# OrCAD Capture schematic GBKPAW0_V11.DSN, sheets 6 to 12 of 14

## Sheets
6 PAGE12:DCINV&P5V: size B
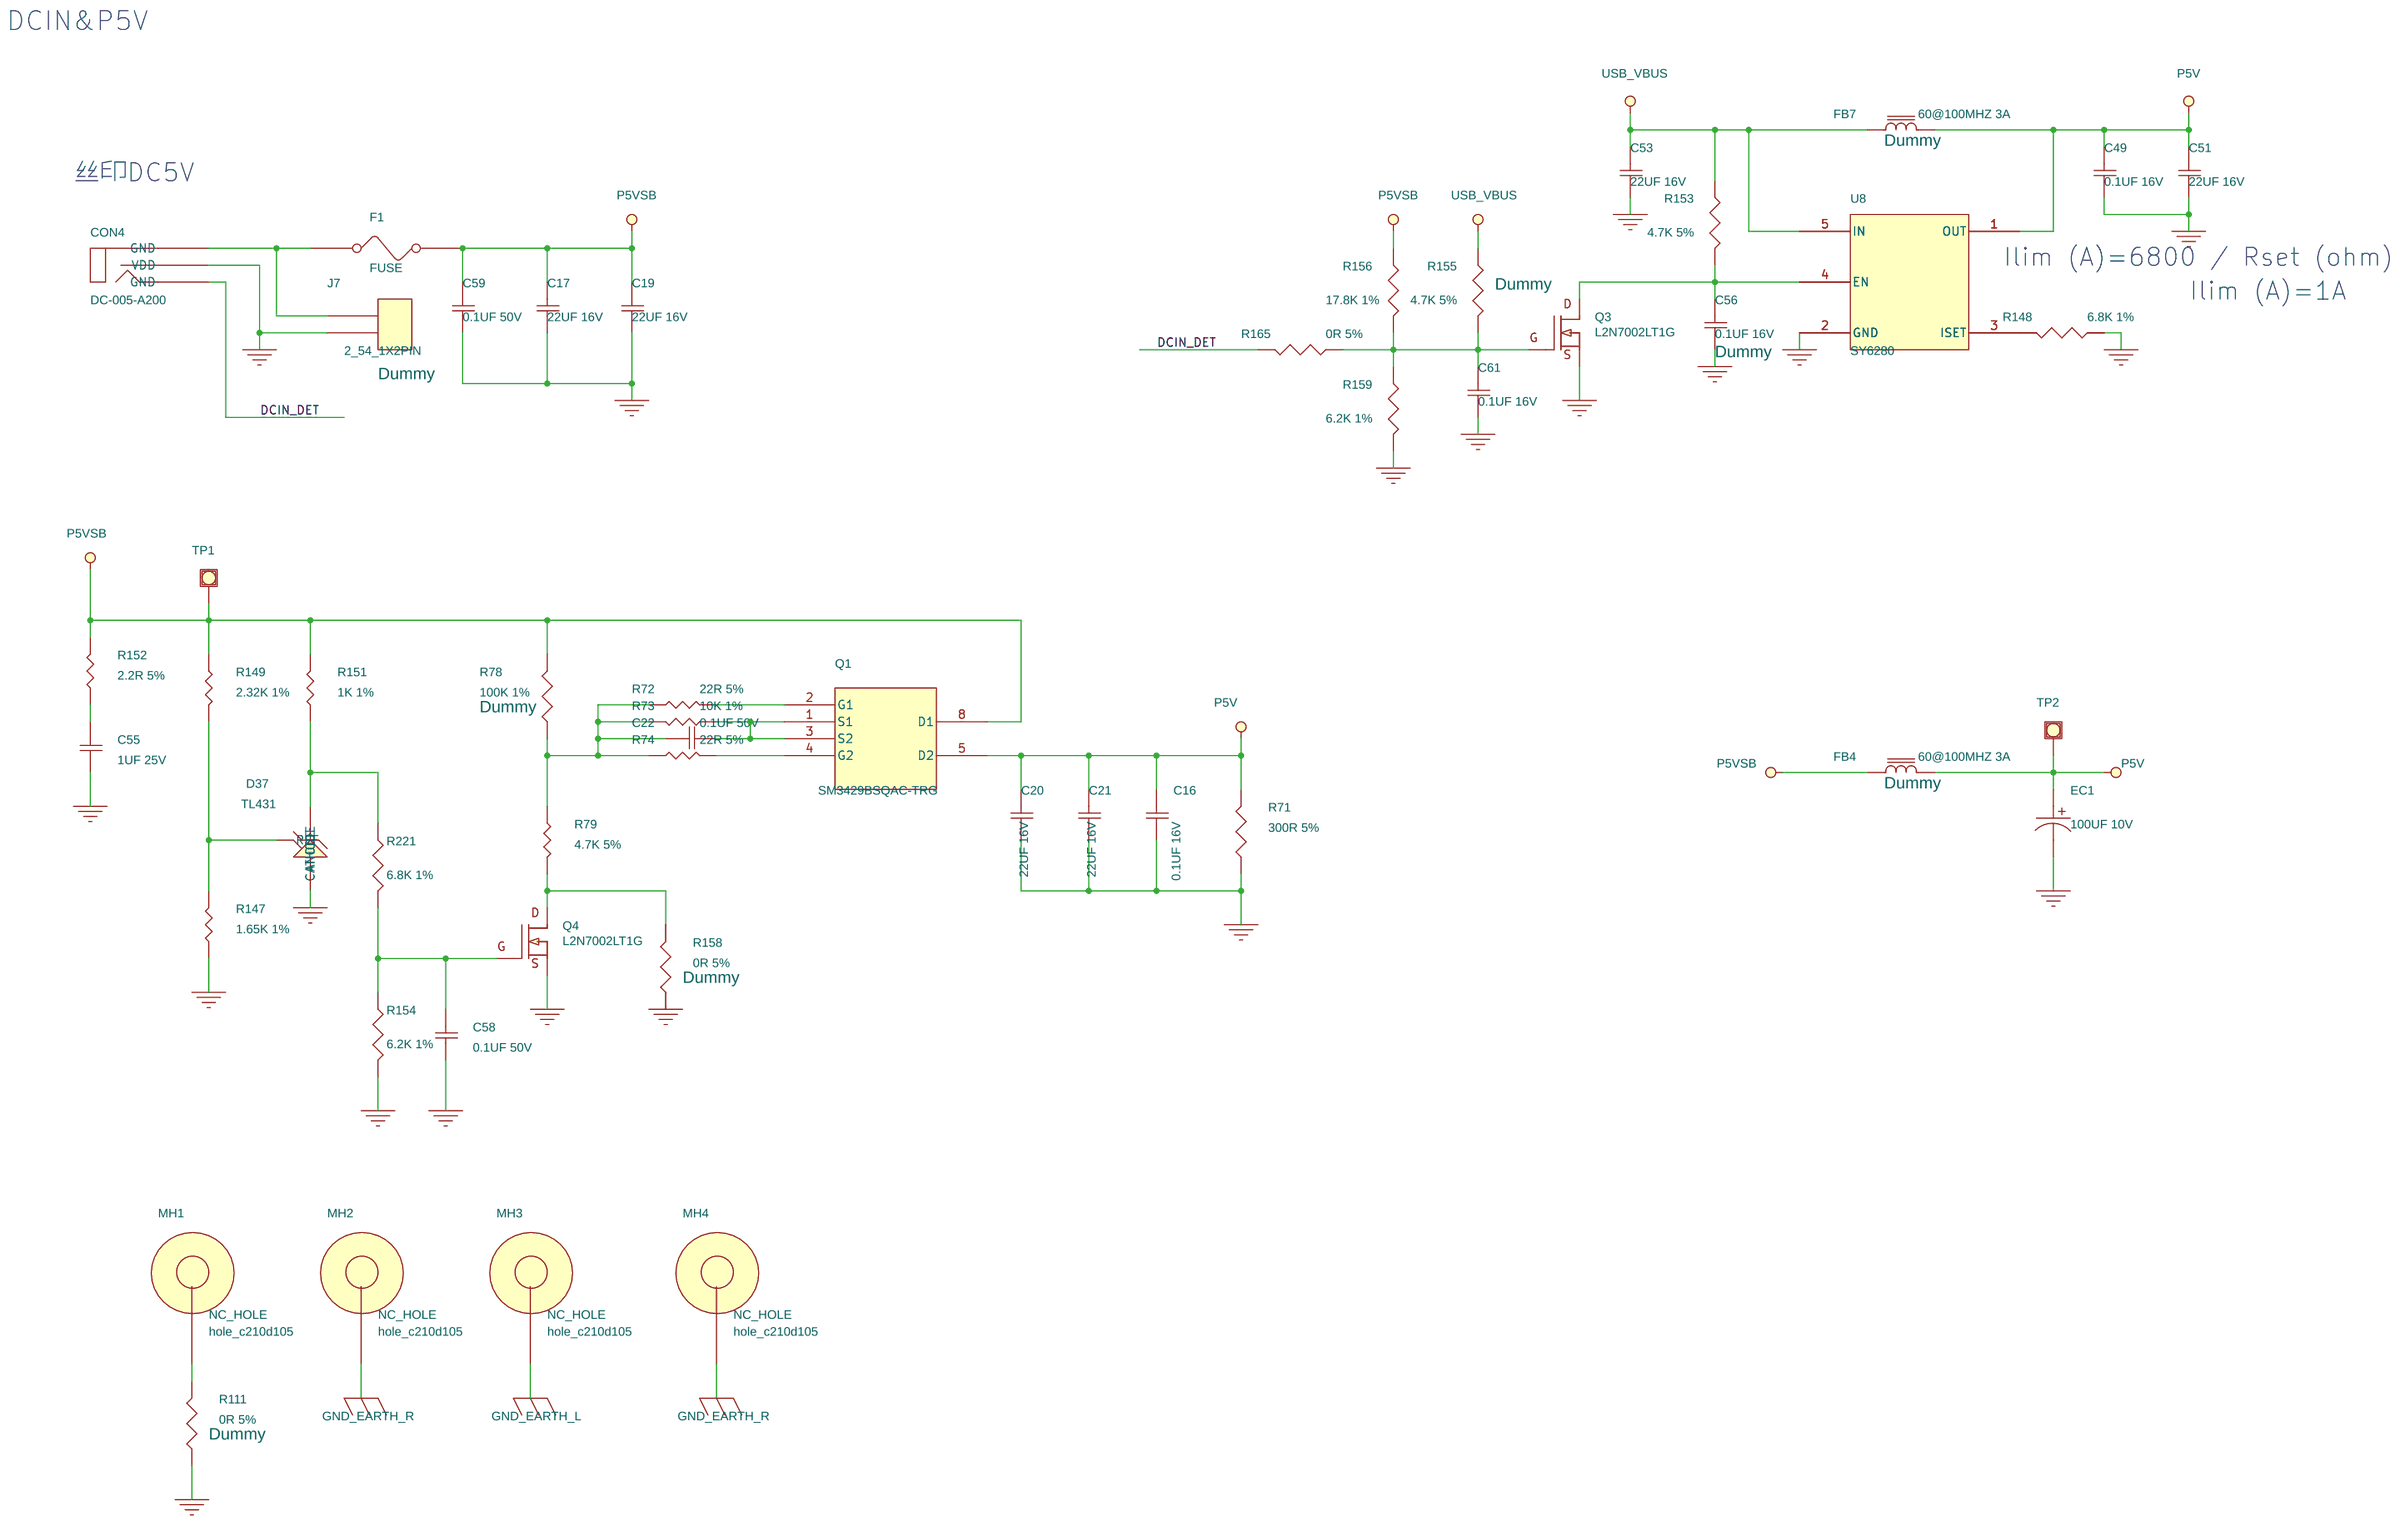
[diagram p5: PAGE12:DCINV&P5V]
7 PAGE10:USB2UART0: size B
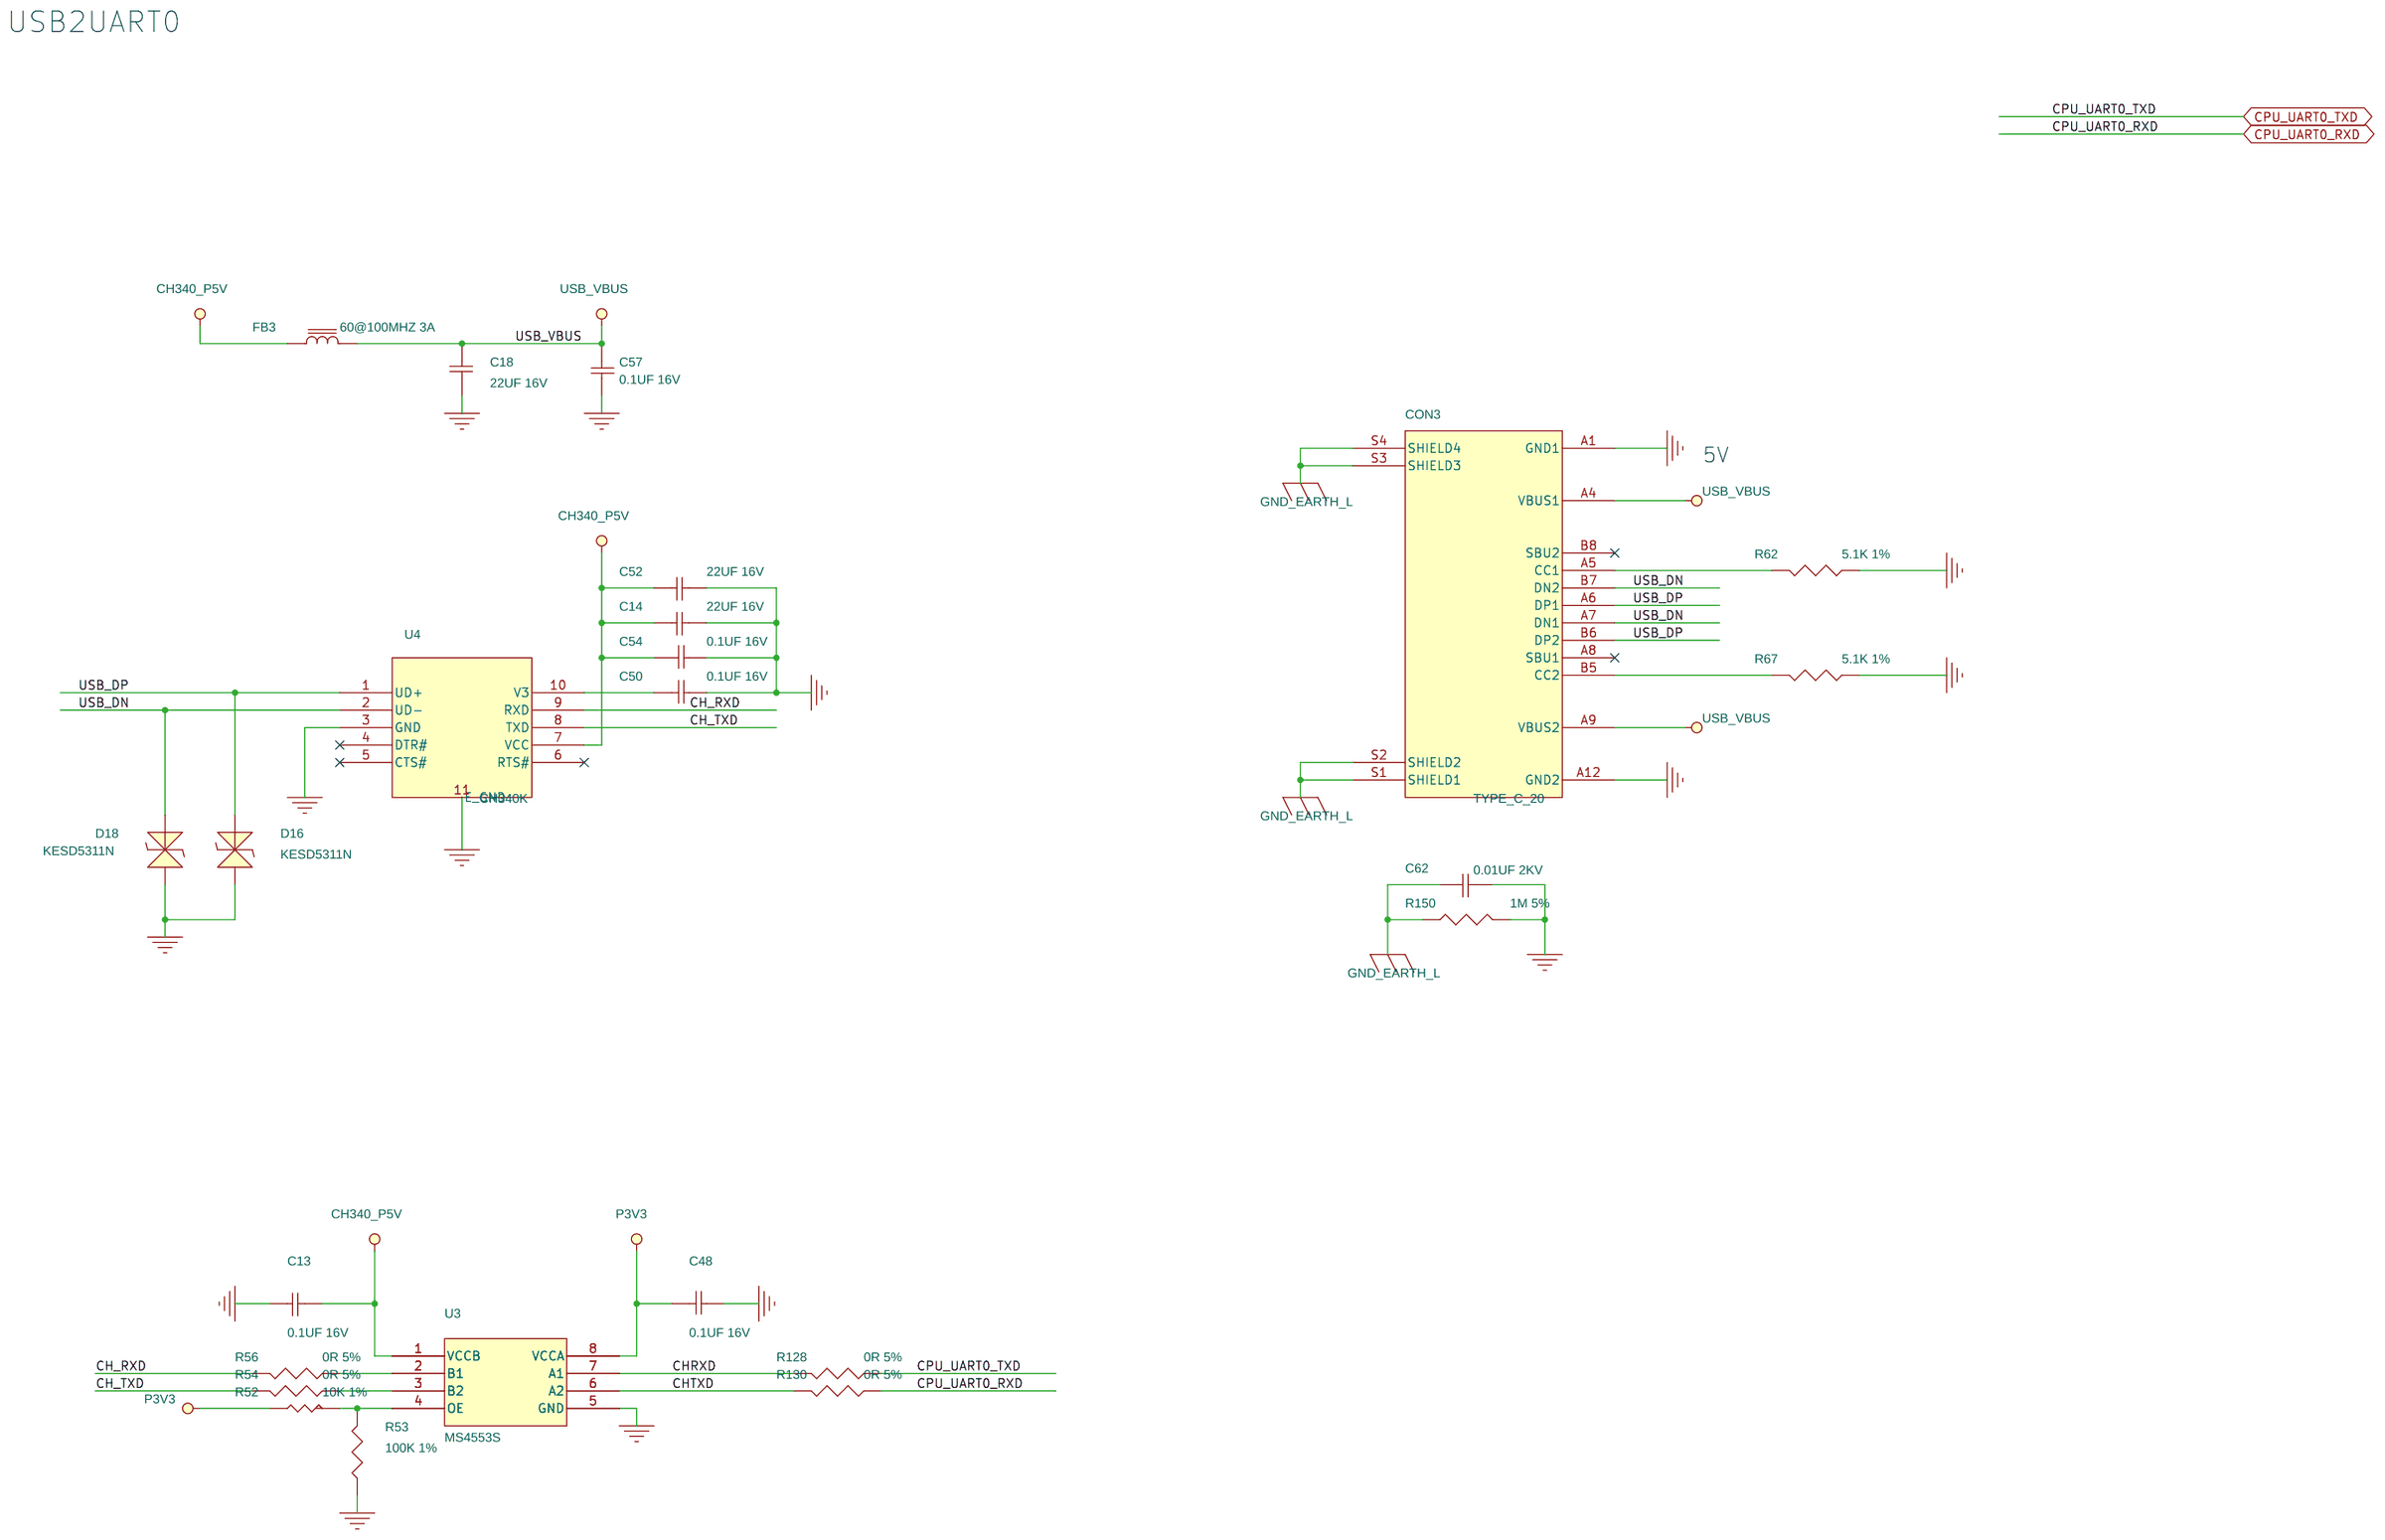
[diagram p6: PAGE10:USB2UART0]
8 PAGE04:CORE_BOARD: size B
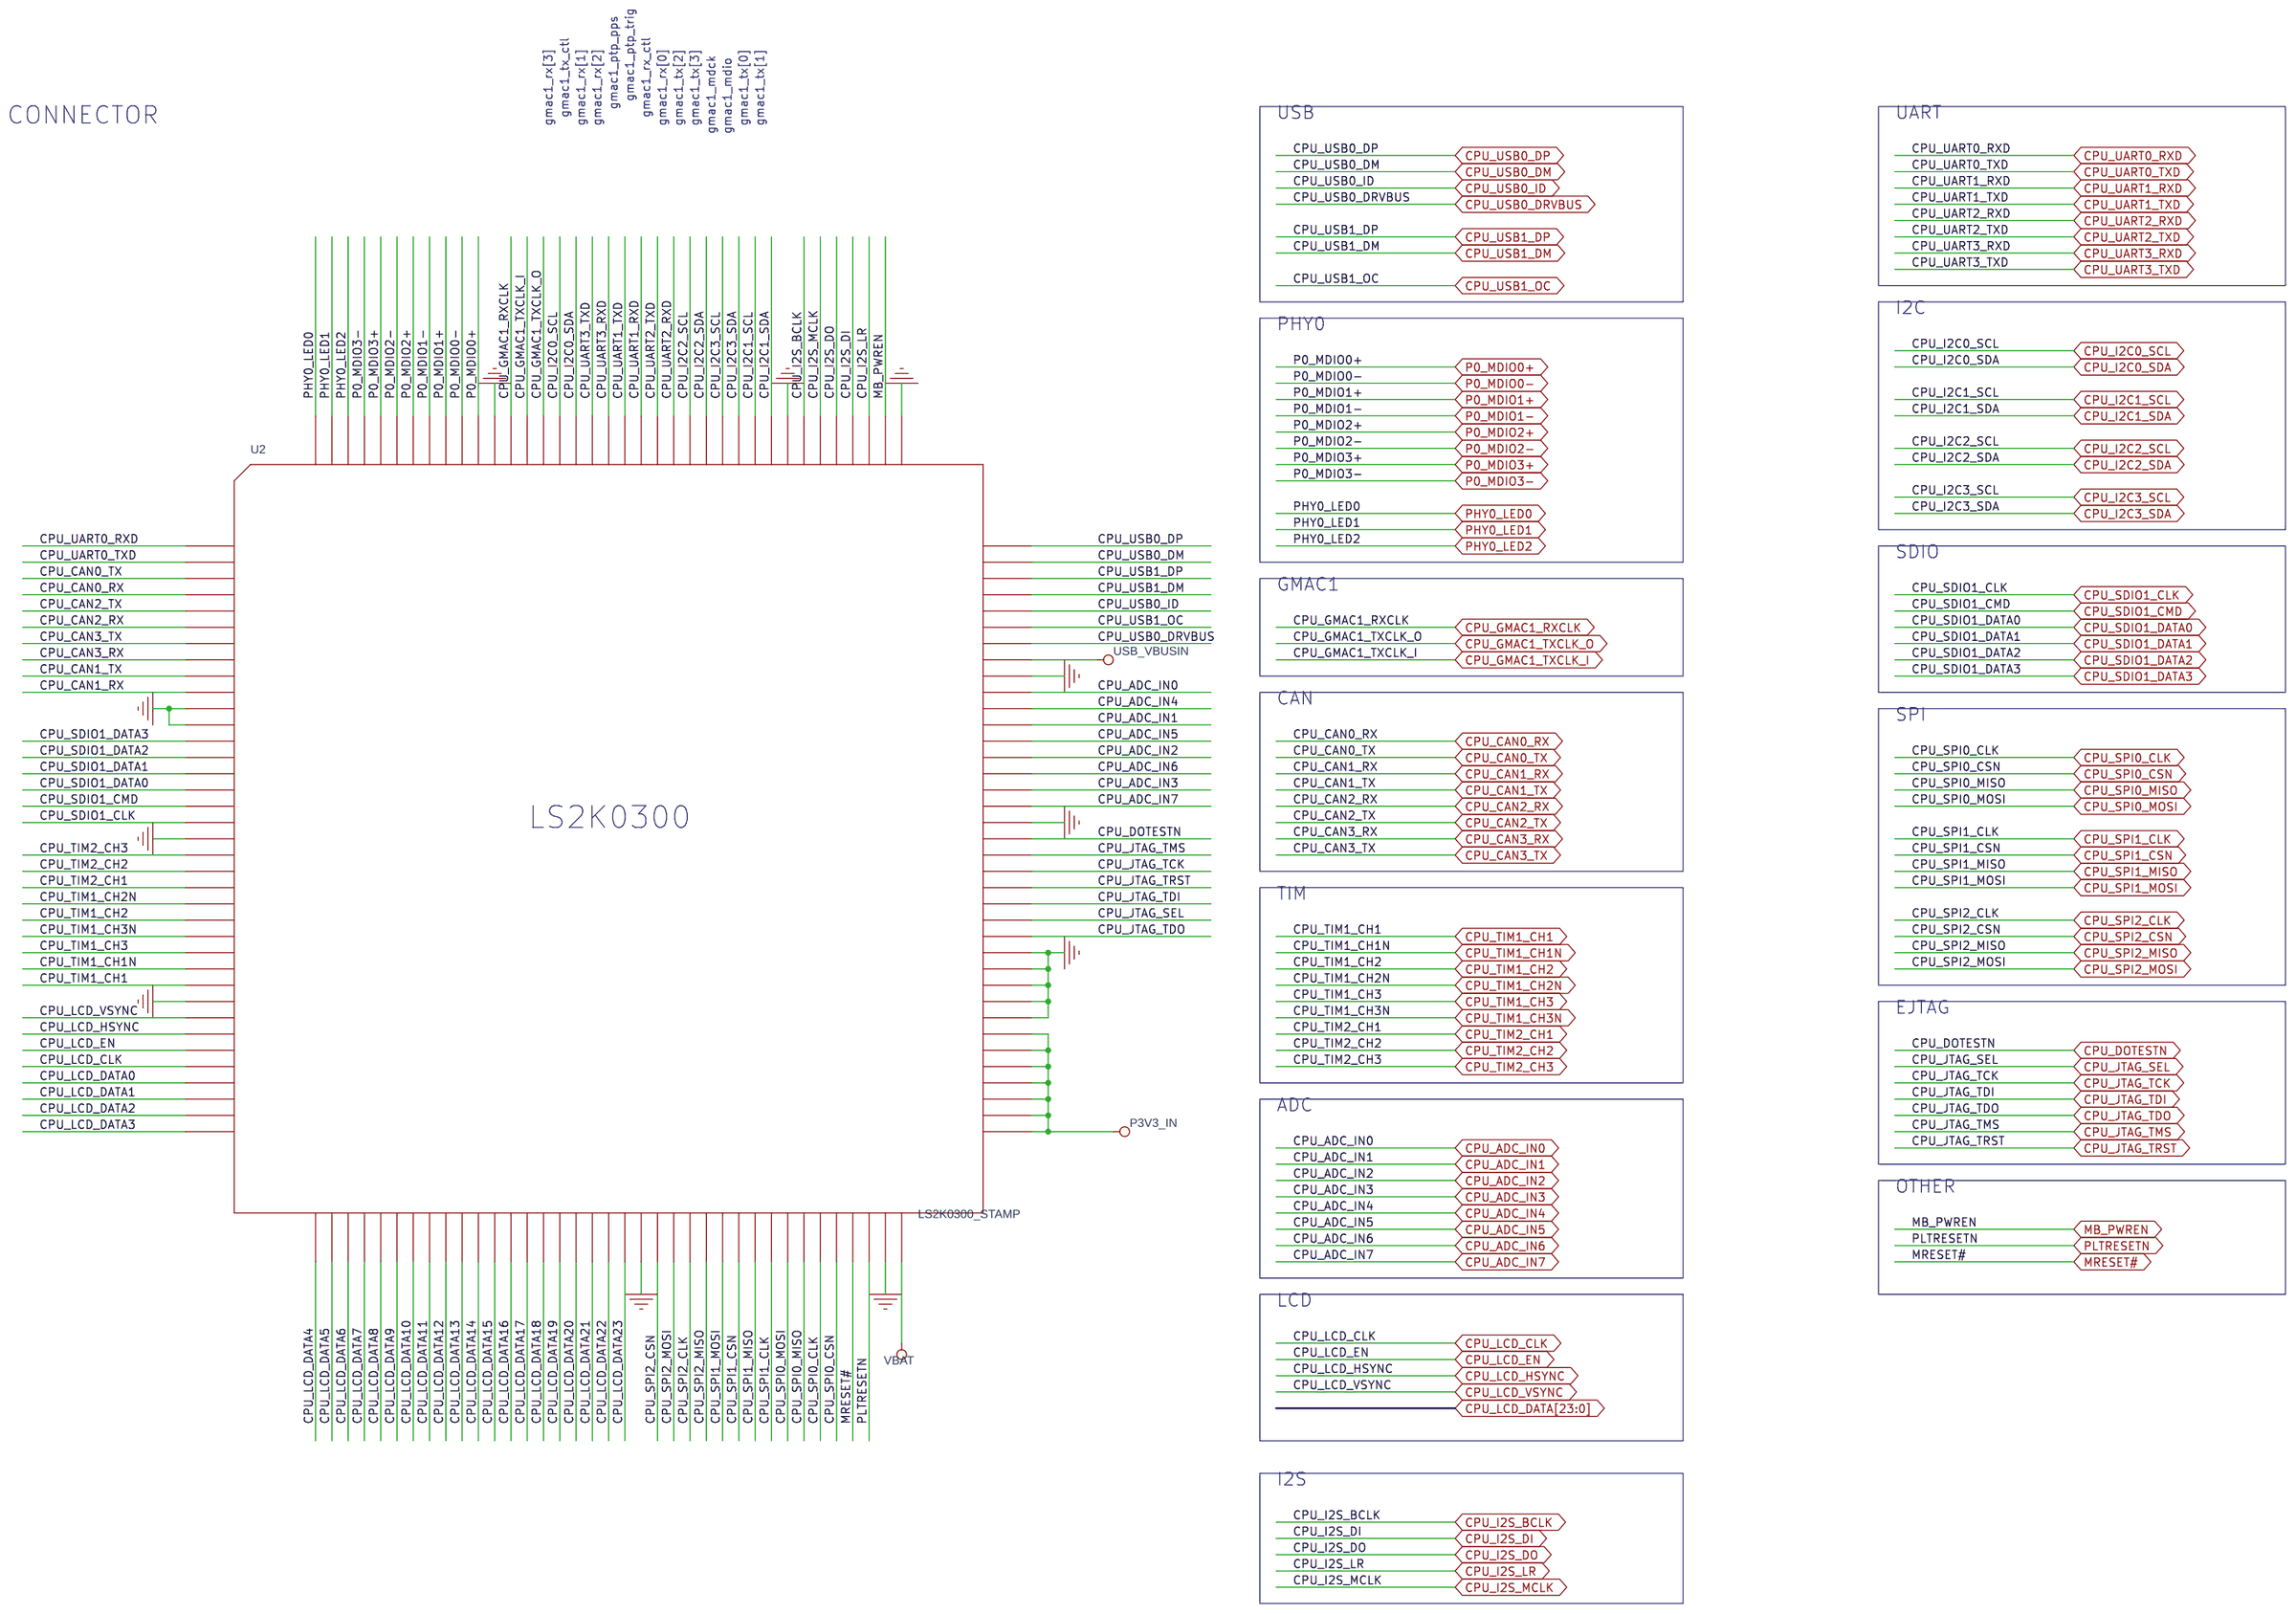
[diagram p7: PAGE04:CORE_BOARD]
9 PAGE11:PIN EXTERNAL: size B
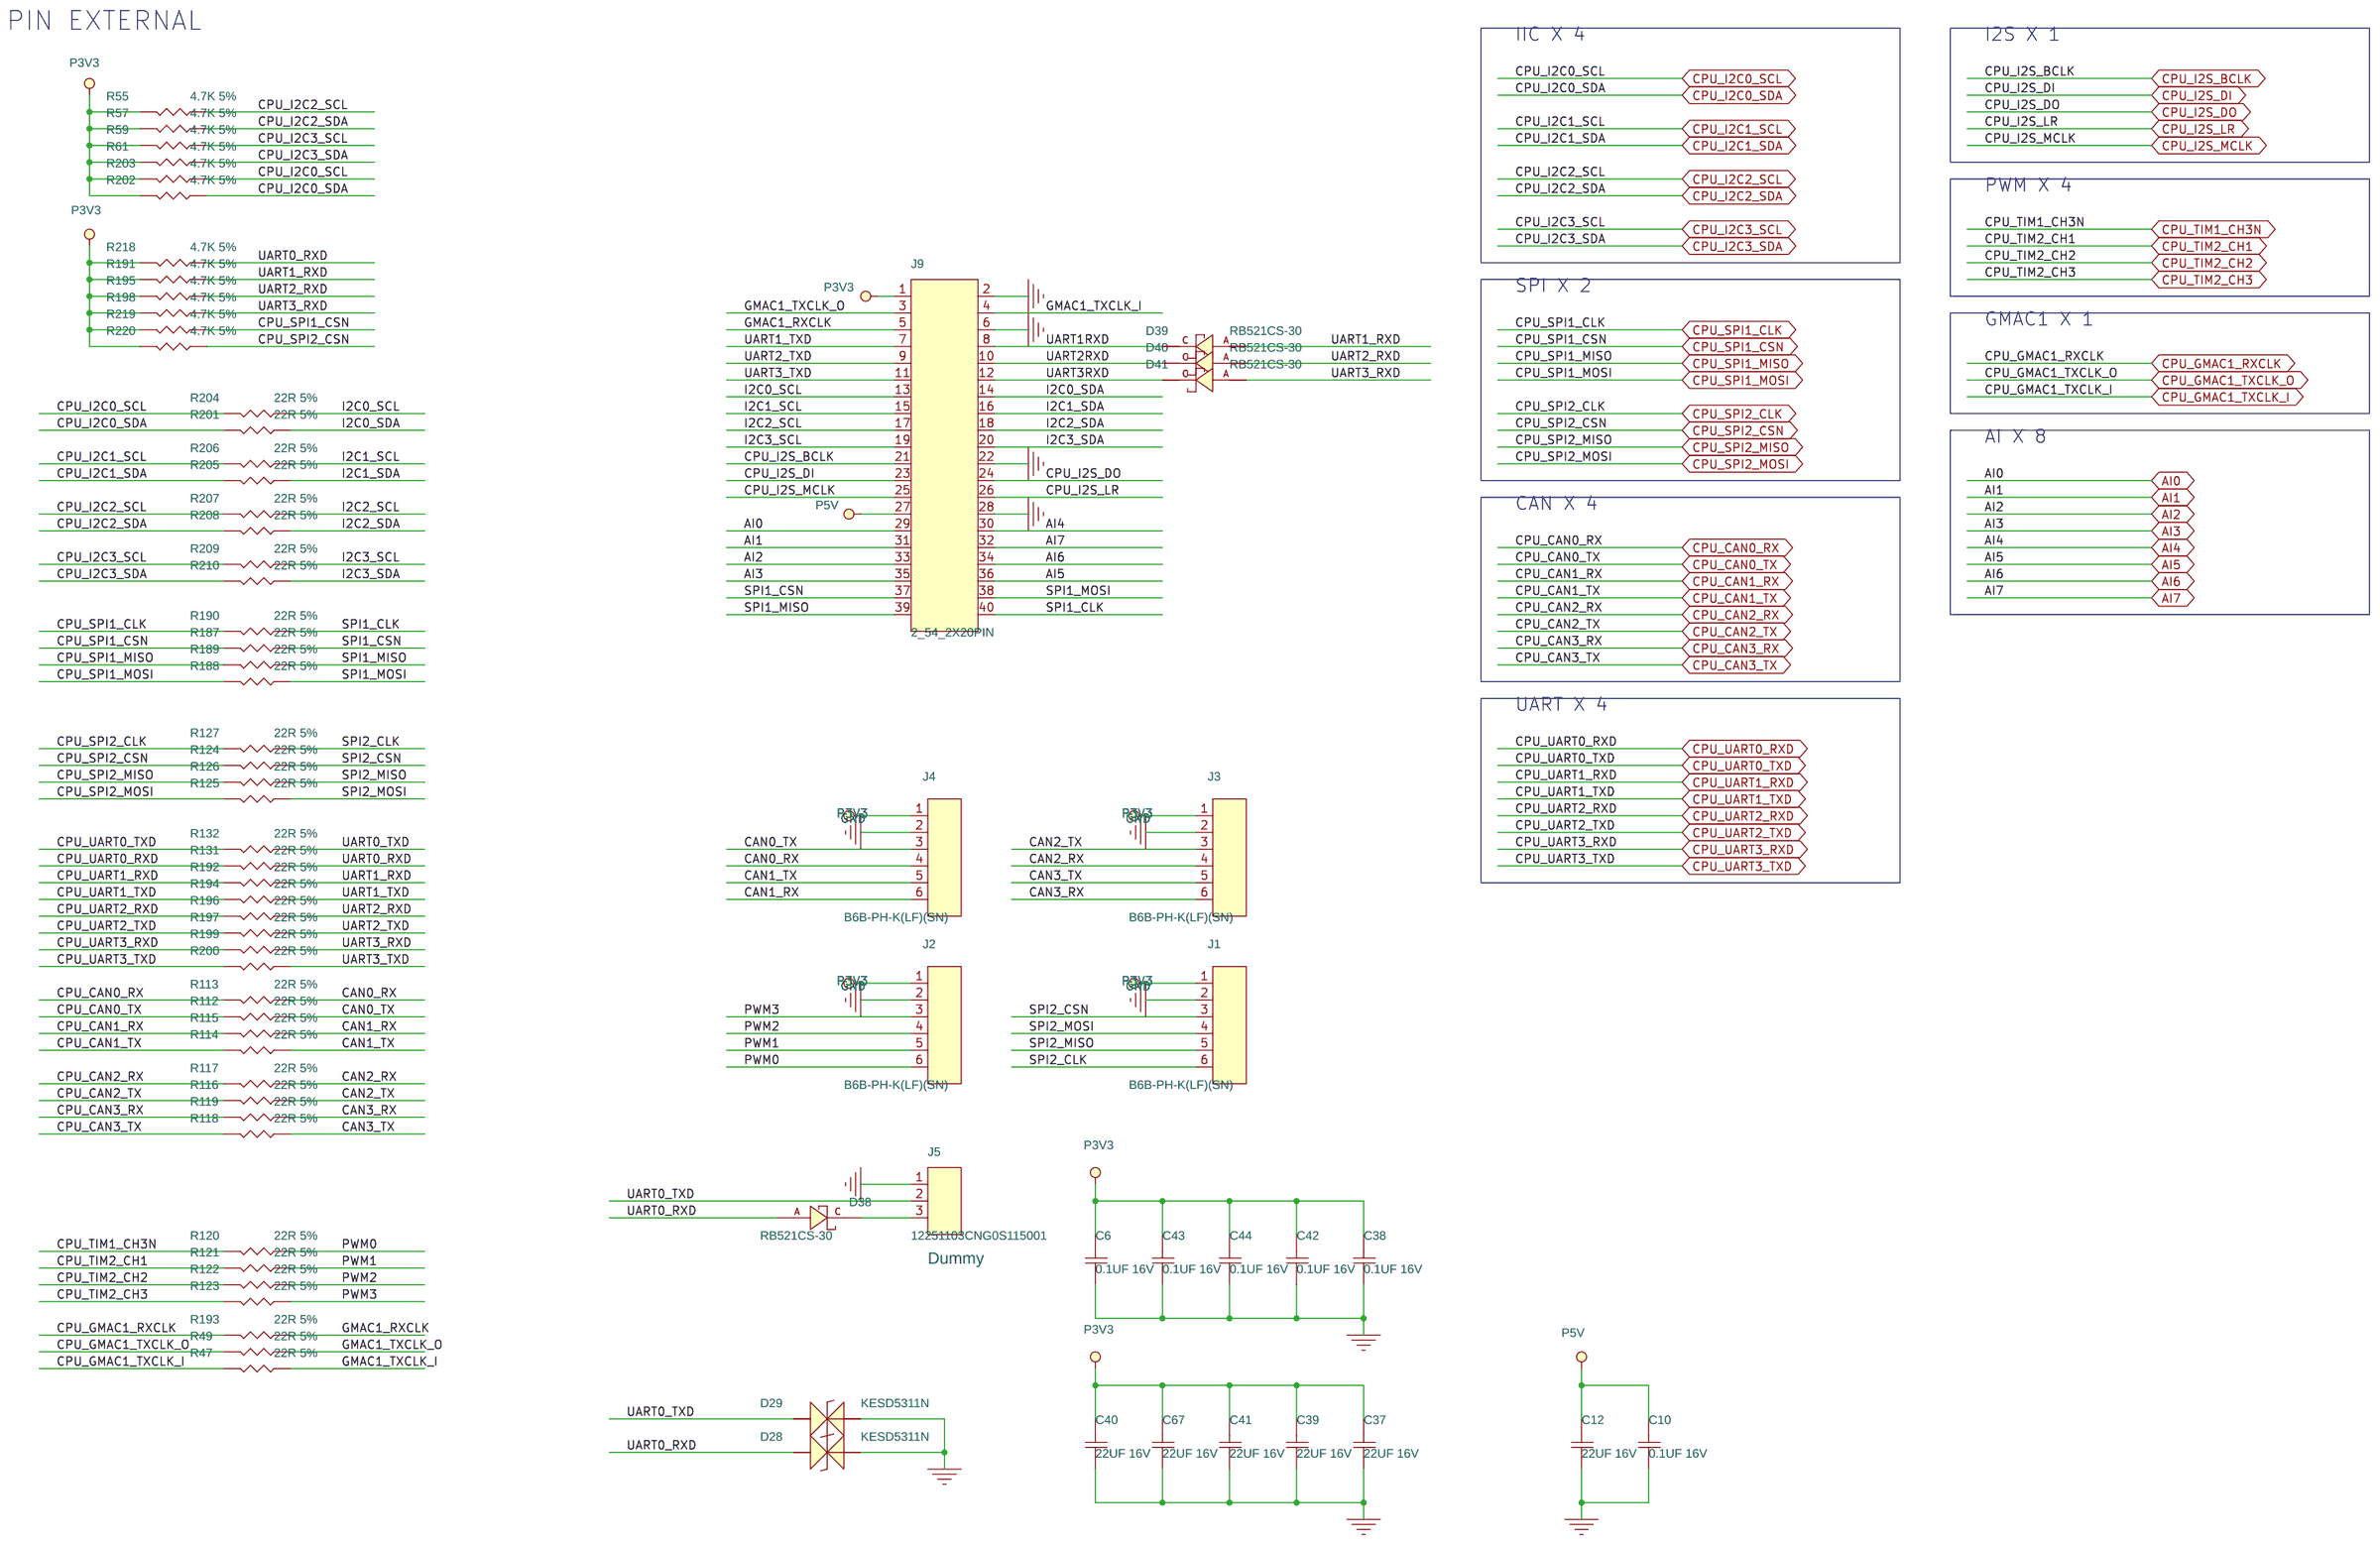
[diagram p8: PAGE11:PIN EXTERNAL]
10 PAGE08:EJTAG&RTC&TF: size B
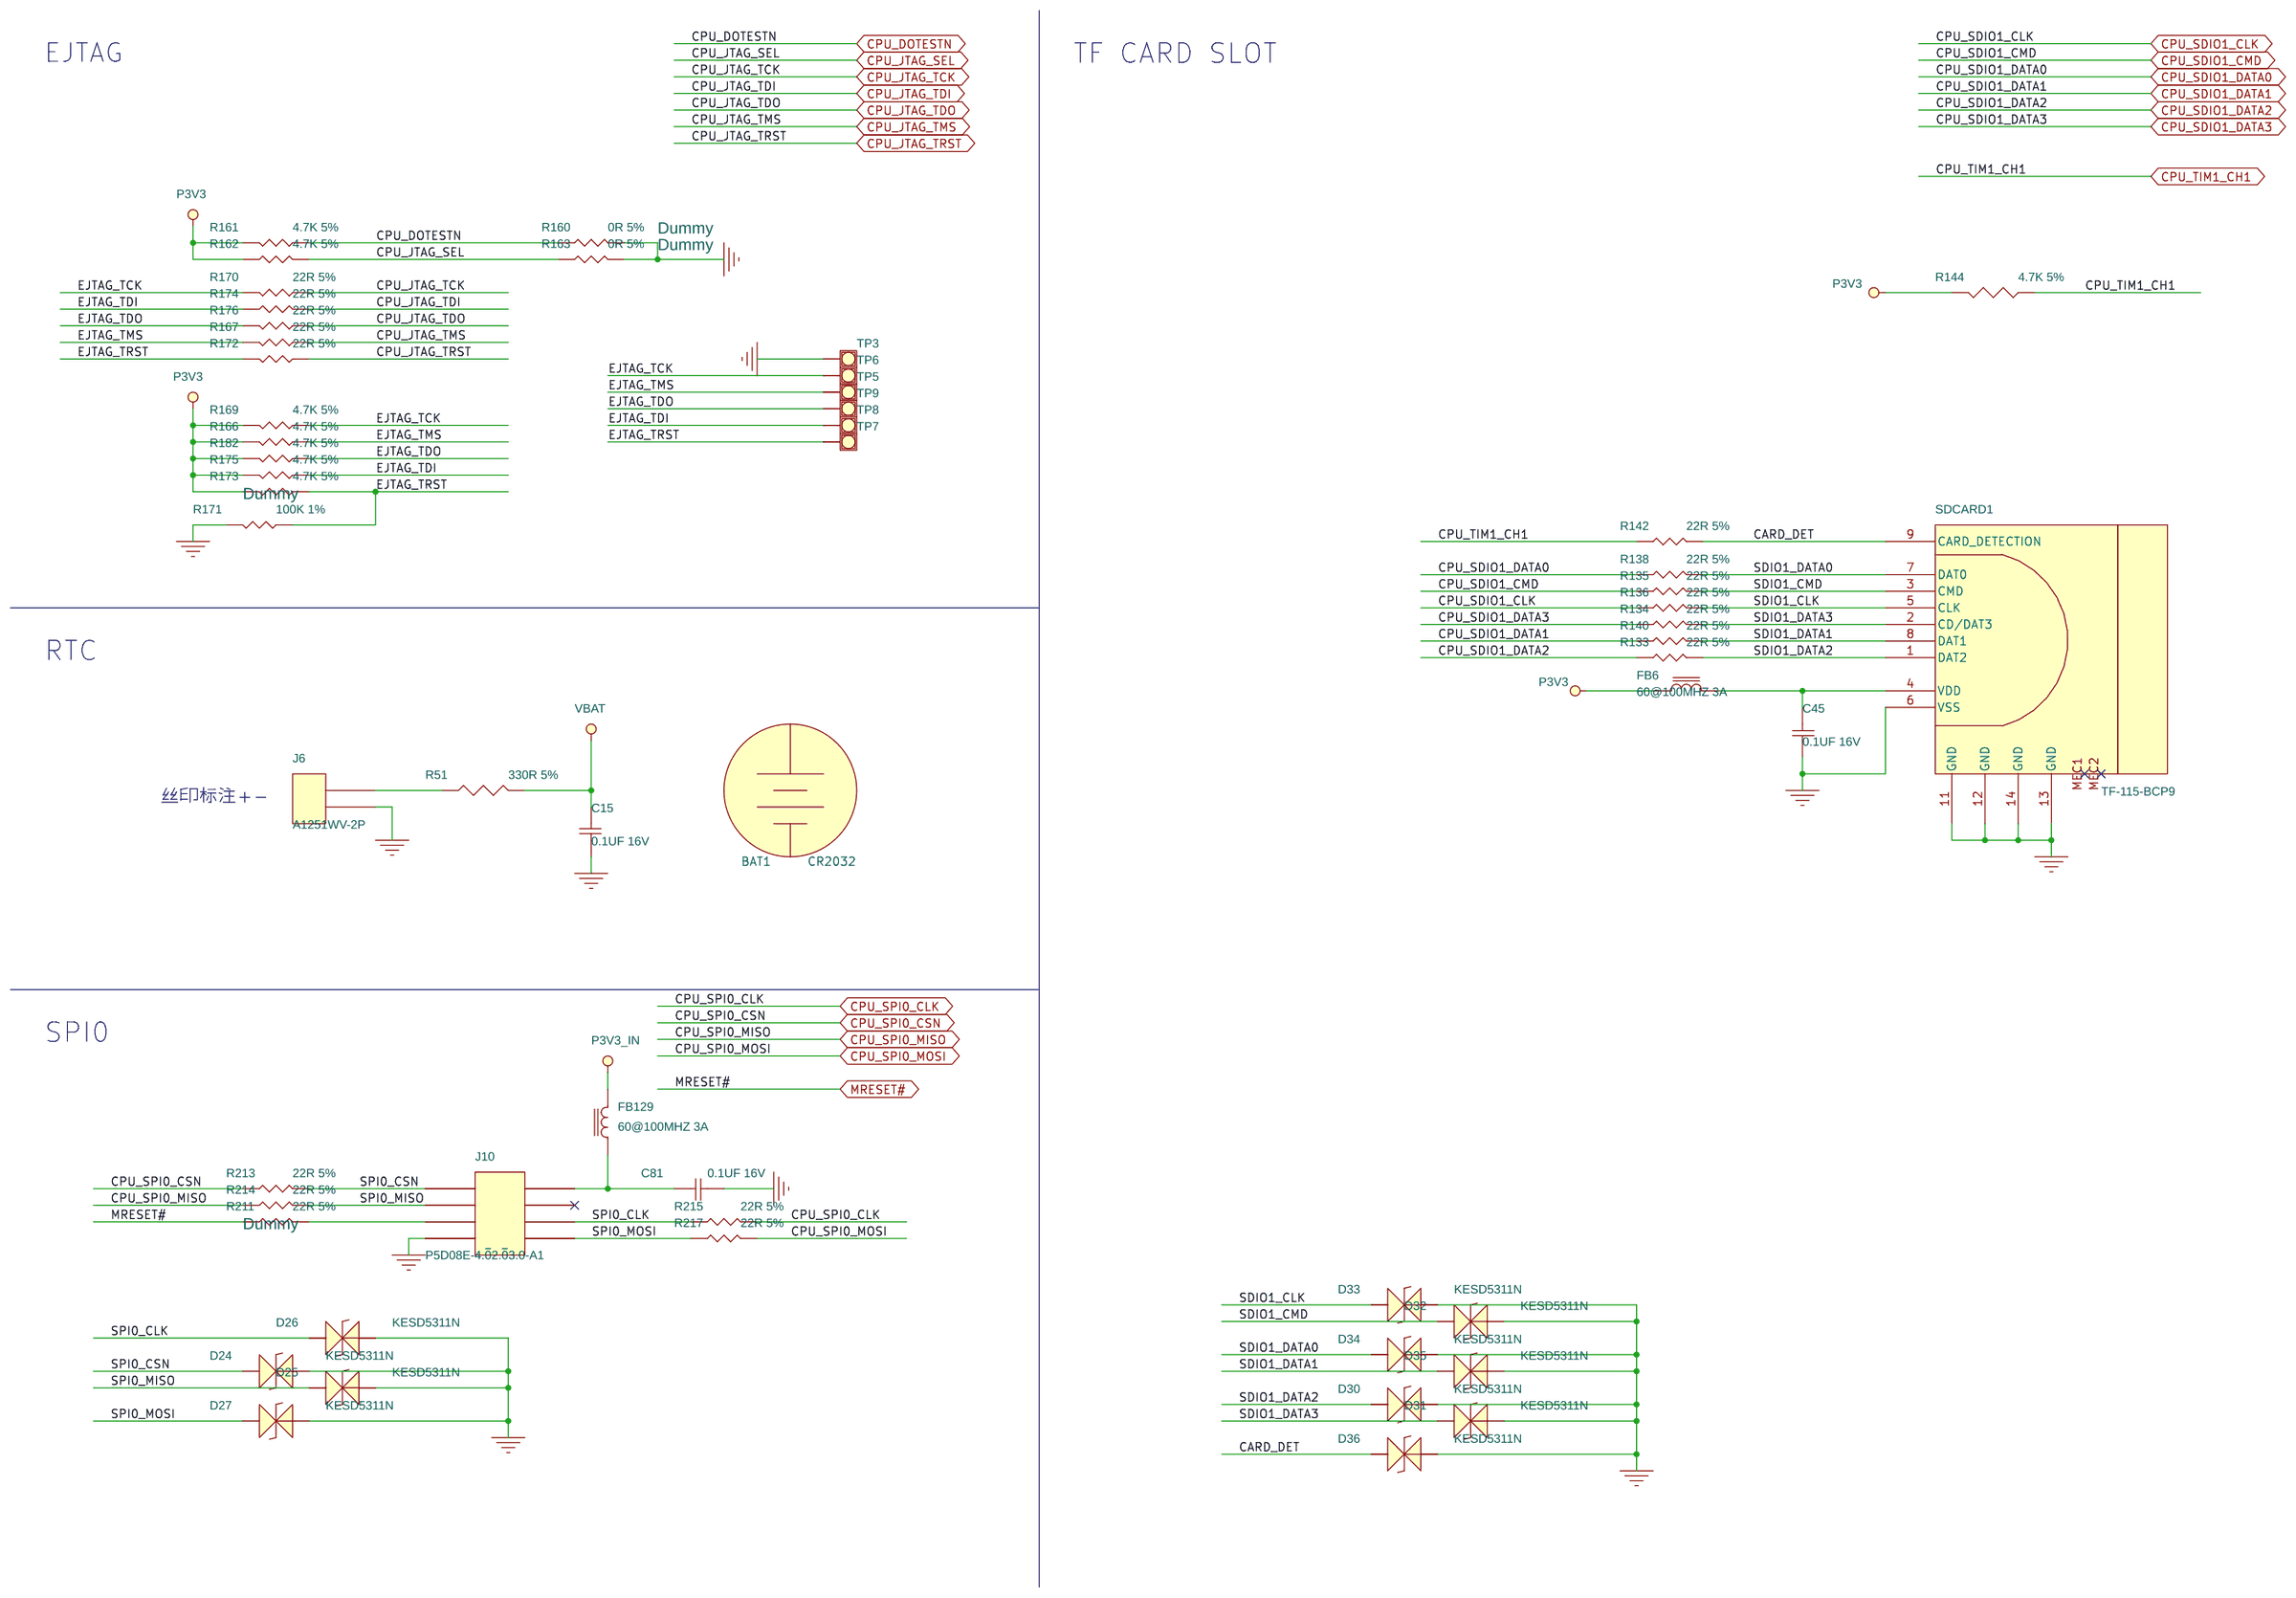
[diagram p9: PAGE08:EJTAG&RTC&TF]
11 PAGE03:POWER DIAGRAM
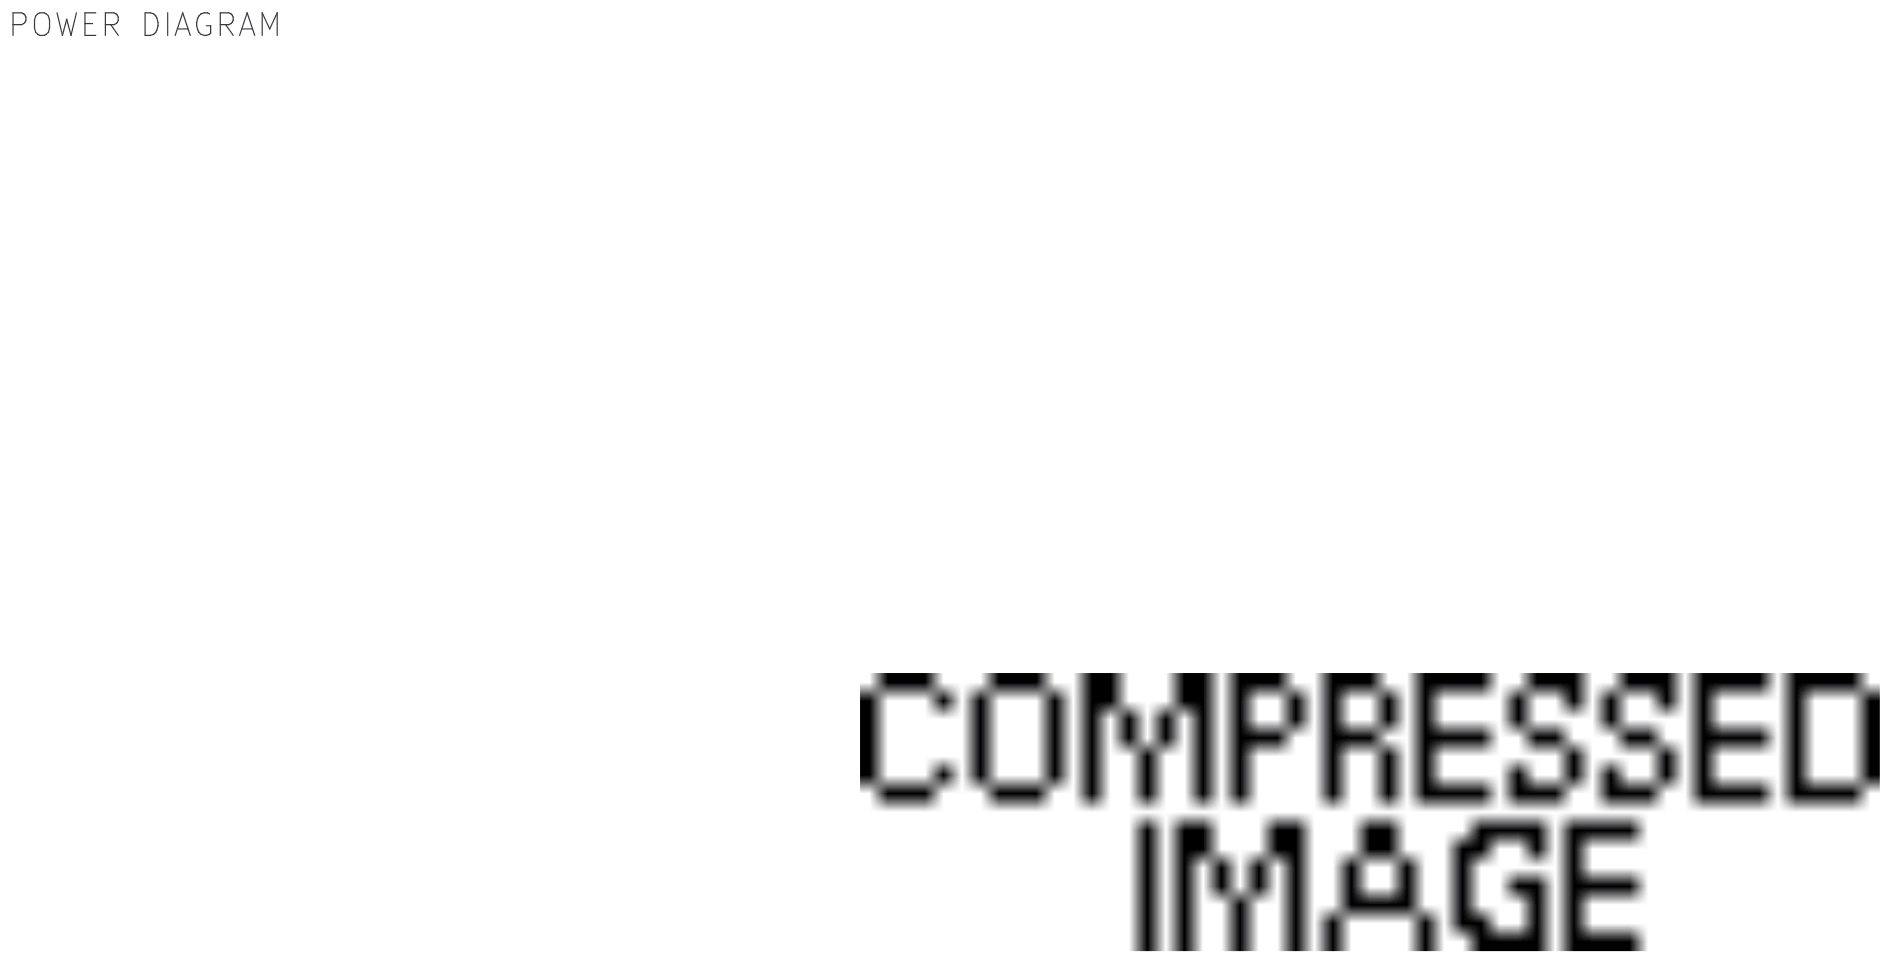
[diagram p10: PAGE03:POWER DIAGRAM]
12 PAGE02:BLOCK DIAGRAM
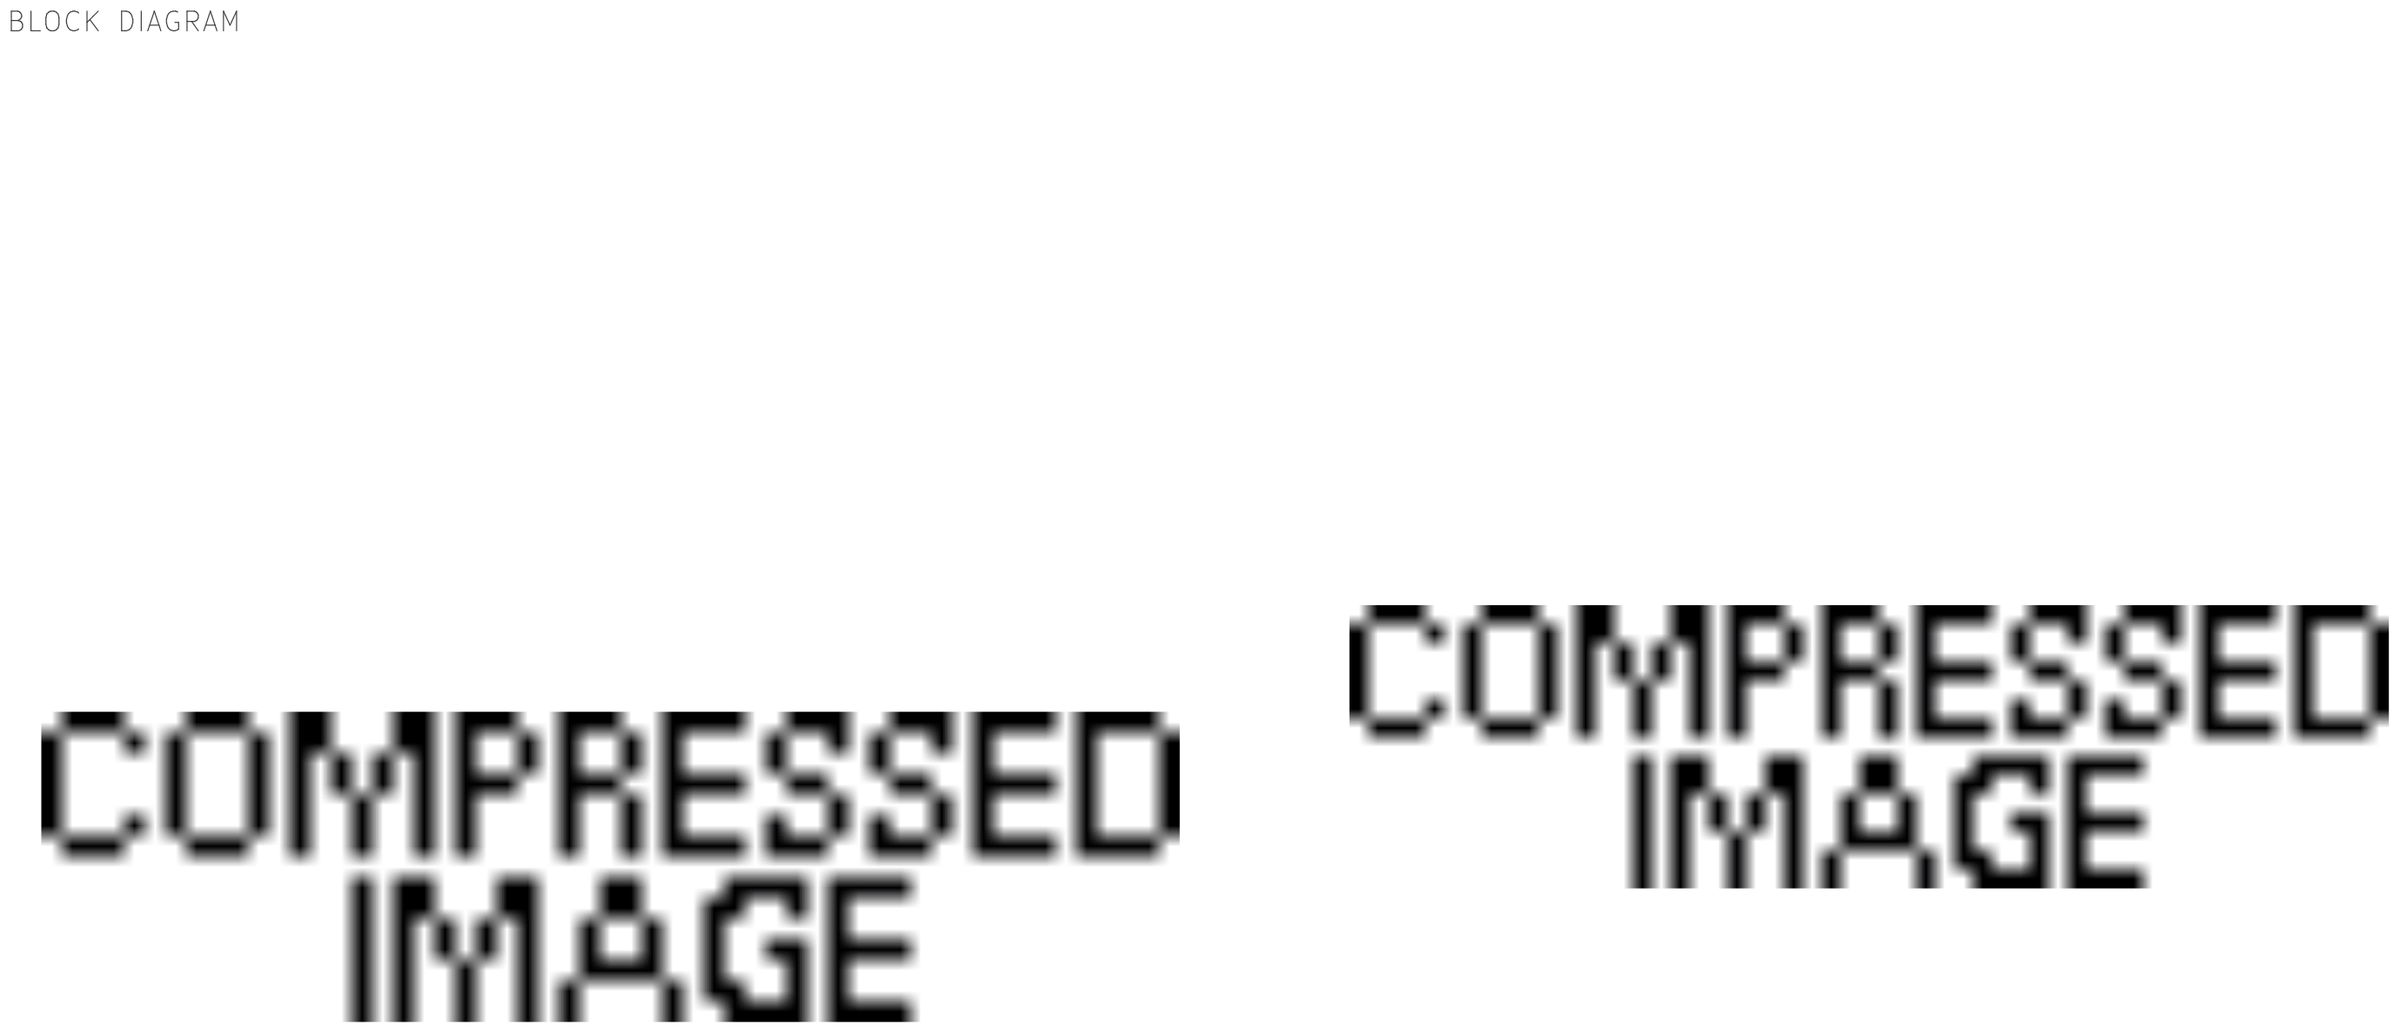
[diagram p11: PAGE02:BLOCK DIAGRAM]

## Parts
sheet PAGE04:CORE_BOARD
U2  LS2K0300_STAMP  [LS2K0300_STAMP]
sheet PAGE08:EJTAG&RTC&TF
BAT1  CR2032  [NONE]
C15  0.1UF 16V  [C0402]
C45  0.1UF 16V  [C0402]
C81  0.1UF 16V  [C0402]
D24  KESD5311N  [ESDPSA-0402]
D25  KESD5311N  [ESDPSA-0402]
D26  KESD5311N  [ESDPSA-0402]
D27  KESD5311N  [ESDPSA-0402]
D30  KESD5311N  [ESDPSA-0402]
D31  KESD5311N  [ESDPSA-0402]
D32  KESD5311N  [ESDPSA-0402]
D33  KESD5311N  [ESDPSA-0402]
D34  KESD5311N  [ESDPSA-0402]
D35  KESD5311N  [ESDPSA-0402]
D36  KESD5311N  [ESDPSA-0402]
FB6  60@100MHZ 3A  [FB0603]
FB129  60@100MHZ 3A  [FB0402]
J6  A1251WV-2P  [BHEAD1X2_1]
J10  P5D08E-4.0\2.0\3.0-A1  [HEAD4X2-79]
R51  330R 5%  [R0603]
R133  22R 5%  [R0402]
R134  22R 5%  [R0402]
R135  22R 5%  [R0402]
R136  22R 5%  [R0402]
R138  22R 5%  [R0402]
R140  22R 5%  [R0402]
R142  22R 5%  [R0402]
R144  4.7K 5%  [R0402]
R160  0R 5%  [R0402]
R161  4.7K 5%  [R0402]
R162  4.7K 5%  [R0402]
R163  0R 5%  [R0402]
R166  4.7K 5%  [R0402]
R167  22R 5%  [R0402]
R169  4.7K 5%  [R0402]
R170  22R 5%  [R0402]
R171  100K 1%  [R0402]
R172  22R 5%  [R0402]
R173  4.7K 5%  [R0402]
R174  22R 5%  [R0402]
R175  4.7K 5%  [R0402]
R176  22R 5%  [R0402]
R182  4.7K 5%  [R0402]
R211  22R 5%  [R0402]
R213  22R 5%  [R0402]
R214  22R 5%  [R0402]
R215  22R 5%  [R0402]
R217  22R 5%  [R0402]
SDCARD1  TF-115-BCP9  [SDCARD8_3]
TP3  X_SD_TSTR  [TP-SMD]
TP5  X_SD_TSTR  [TP-SMD]
TP6  X_SD_TSTR  [TP-SMD]
TP7  X_SD_TSTR  [TP-SMD]
TP8  X_SD_TSTR  [TP-SMD]
TP9  X_SD_TSTR  [TP-SMD]
sheet PAGE10:USB2UART0
C13  0.1UF 16V  [C0402]
C14  22UF 16V  [C0805]
C18  22UF 16V  [C0805]
C48  0.1UF 16V  [C0402]
C50  0.1UF 16V  [C0402]
C52  22UF 16V  [C0805]
C54  0.1UF 16V  [C0402]
C57  0.1UF 16V  [C0402]
C62  0.01UF 2KV  [C1206]
CON3  TYPE_C_20  [TYPE_C_20_2]
D16  KESD5311N  [ESDPSA-0402]
D18  KESD5311N  [ESDPSA-0402]
FB3  60@100MHZ 3A  [FB0603]
R52  10K 1%  [R0402]
R53  100K 1%  [R0402]
R54  0R 5%  [R0402]
R56  0R 5%  [R0402]
R62  5.1K 1%  [R0402]
R67  5.1K 1%  [R0402]
R128  0R 5%  [R0402]
R130  0R 5%  [R0402]
R150  1M 5%  [R0603]
U3  MS4553S  [SOT23-8]
U4  CH340K  [essop10_smd77x124]
sheet PAGE11:PIN EXTERNAL
C6  0.1UF 16V  [C0402]
C10  0.1UF 16V  [C0402]
C12  22UF 16V  [C0805]
C37  22UF 16V  [C0805]
C38  0.1UF 16V  [C0402]
C39  22UF 16V  [C0805]
C40  22UF 16V  [C0805]
C41  22UF 16V  [C0805]
C42  0.1UF 16V  [C0402]
C43  0.1UF 16V  [C0402]
C44  0.1UF 16V  [C0402]
C67  22UF 16V  [C0805]
D28  KESD5311N  [ESDPSA-0402]
D29  KESD5311N  [ESDPSA-0402]
D38  RB521CS-30  [DIODE_SOD923]
D39  RB521CS-30  [DIODE_SOD923]
D40  RB521CS-30  [DIODE_SOD923]
D41  RB521CS-30  [DIODE_SOD923]
J1  B6B-PH-K(LF)(SN)  [BHEAD1X6_2MM_2]
J2  B6B-PH-K(LF)(SN)  [BHEAD1X6_2MM_2]
J3  B6B-PH-K(LF)(SN)  [BHEAD1X6_2MM_2]
J4  B6B-PH-K(LF)(SN)  [BHEAD1X6_2MM_2]
J5  12251103CNG0S115001  [HEAD3-100-N]
J9  2_54_2X20PIN  [HEADER20X2-100]
R47  22R 5%  [R0402]
R49  22R 5%  [R0402]
R55  4.7K 5%  [R0402]
R57  4.7K 5%  [R0402]
R59  4.7K 5%  [R0402]
R61  4.7K 5%  [R0402]
R112  22R 5%  [R0402]
R113  22R 5%  [R0402]
R114  22R 5%  [R0402]
R115  22R 5%  [R0402]
R116  22R 5%  [R0402]
R117  22R 5%  [R0402]
R118  22R 5%  [R0402]
R119  22R 5%  [R0402]
R120  22R 5%  [R0402]
R121  22R 5%  [R0402]
R122  22R 5%  [R0402]
R123  22R 5%  [R0402]
R124  22R 5%  [R0402]
R125  22R 5%  [R0402]
R126  22R 5%  [R0402]
R127  22R 5%  [R0402]
R131  22R 5%  [R0402]
R132  22R 5%  [R0402]
R187  22R 5%  [R0402]
R188  22R 5%  [R0402]
R189  22R 5%  [R0402]
R190  22R 5%  [R0402]
R191  4.7K 5%  [R0402]
R192  22R 5%  [R0402]
R193  22R 5%  [R0402]
R194  22R 5%  [R0402]
R195  4.7K 5%  [R0402]
R196  22R 5%  [R0402]
R197  22R 5%  [R0402]
R198  4.7K 5%  [R0402]
R199  22R 5%  [R0402]
R200  22R 5%  [R0402]
R201  22R 5%  [R0402]
R202  4.7K 5%  [R0402]
R203  4.7K 5%  [R0402]
R204  22R 5%  [R0402]
R205  22R 5%  [R0402]
R206  22R 5%  [R0402]
R207  22R 5%  [R0402]
R208  22R 5%  [R0402]
R209  22R 5%  [R0402]
R210  22R 5%  [R0402]
R218  4.7K 5%  [R0402]
R219  4.7K 5%  [R0402]
R220  4.7K 5%  [R0402]
sheet PAGE12:DCINV&P5V
C16  0.1UF 16V  [C0402]
C17  22UF 16V  [C0805]
C19  22UF 16V  [C0805]
C20  22UF 16V  [C0805]
C21  22UF 16V  [C0805]
C22  0.1UF 50V  [C0603]
C49  0.1UF 16V  [C0402]
C51  22UF 16V  [C0805]
C53  22UF 16V  [C0805]
C55  1UF 25V  [C0603]
C56  0.1UF 16V  [C0402]
C58  0.1UF 50V  [C0603]
C59  0.1UF 50V  [C0603]
C61  0.1UF 16V  [C0402]
CON4  DC-005-A200  [PWC3-250_2]
D37  TL431  [SOT23-3]
EC1  100UF 10V  [TC3528-21]
F1  FUSE  [FUSE1206]
FB4  60@100MHZ 3A  [FB0603]
FB7  60@100MHZ 3A  [FB0603]
J7  2_54_1X2PIN  [BHEAD1X2_2_54MM]
MH1  NC_HOLE  [hole_c210d105]
MH2  NC_HOLE  [hole_c210d105]
MH3  NC_HOLE  [hole_c210d105]
MH4  NC_HOLE  [hole_c210d105]
Q1  SM3429BSQAC-TRG  [DFN6_3X3]
Q3  L2N7002LT1G  [SOT23-3]
Q4  L2N7002LT1G  [SOT23-3]
R71  300R 5%  [R0805]
R72  22R 5%  [R0402]
R73  10K 1%  [R0402]
R74  22R 5%  [R0402]
R78  100K 1%  [R0402]
R79  4.7K 5%  [R0402]
R111  0R 5%  [R0402]
R147  1.65K 1%  [R0402]
R148  6.8K 1%  [R0402]
R149  2.32K 1%  [R0402]
R151  1K 1%  [R0402]
R152  2.2R 5%  [R0603]
R153  4.7K 5%  [R0402]
R154  6.2K 1%  [R0402]
R155  4.7K 5%  [R0402]
R156  17.8K 1%  [R0402]
R158  0R 5%  [R0402]
R159  6.2K 1%  [R0402]
R165  0R 5%  [R0402]
R221  6.8K 1%  [R0402]
TP1  X_SD_TSTR  [TP-SMD]
TP2  X_SD_TSTR  [TP-SMD]
U8  SY6280  [SOT23-5]

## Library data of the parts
U2 = LS2K0300_STAMP: CORE BOARD,CPU LS2K0300,1G DDR4,8G EMMC,ROHS; Manufacturer: LOONGSON; Manufacturer PN: G2K03Z0_V10; Option: I; Package type: SMT; Part Number: G2K03Z0_V10; Part Type: BOARD; ROHS: Y; Remark: Reserved; Status: 商业级
BAT1 = BATTERY: RTC BATTERY,2PIN/CR2032MLK+线:1571/28#线,L=60MM,绞,1.25mm,正头,ROHS; Component Name: 纽扣电池,SONY,CR2032; Manufacturer: 深圳迈洛克; Manufacturer PN: 1.C.F.BATX.CR2032-006; Option: I; Package type: ASM; Part Type: 纽扣电池; ROHS: /; Remark: CR2032MLK+线:1571/28#线,L=60MM,绞,1.25mm正头; Status: 商业级; Datasheet: Z:\lib\Datasheet\CR2032.pdf
C13 C15 C16 C48-C50 C54 C57 C61 C81 = C: CAP,MLCC,0.1UF,16V,10%,C0402/SMT,X7R,ROHS; Component Name: 0.1UF 16V C0402 YAGEO CC0402KRX7R7BB104; ID: 22; Manufacturer: YAGEO; Manufacturer PN: CC0402KRX7R7BB104; Option: I; Package type: SMT; Part Number: C111042XK62YG1; Part Type: 陶瓷电容; ROHS: Y; Remark: Reserved; Status: 商业级; Datasheet: D:\lib_ls\Datasheet\RC\YAGEO-C.pdf
C45 = C: CAP,MLCC,0.1UF,16V,10%,C0402/SMT,X7R,ROHS; Component Name: 0.1UF 16V C0402 YAGEO CC0402KRX7R7BB104; Manufacturer: YAGEO; Manufacturer PN: CC0402KRX7R7BB104; Option: I; Package type: SMT; Part Number: C111042XK62YG1; Part Type: 陶瓷电容; ROHS: Y; Remark: Reserved; Status: 商业级; Datasheet: D:\lib\Datasheet\RC\YAGEO-C.pdf
D16 D18 D24-D29 = ESD_DIODE_0: ESD Protection devices,ESDPSA-0402/SMT,ESD protection for high speed data lines,ROHS; Component Name: KUU KESD5311N; ID: 160; Manufacturer: KUU; Option: I; Package type: SMT; Part Number: DJ1ESDPSA12SKU-GZ; Part Type: 瞬态电压抑制二极管; ROHS: Y; Remark: Reserved; Status: 商业级; Datasheet: D:\lib_ls\Datasheet\KESD5311N.PDF
D30-D36 = ESD_DIODE_0: ESD Protection devices,ESDPSA-0402/SMT,ESD protection for high speed data lines,ROHS; Component Name: KUU KESD5311N; ID: 160; Manufacturer: KUU; Option: I; Package type: SMT; Part Number: DJ1ESDPSA12SKU-GZ; Part Type: 瞬态电压抑制二极管; ROHS: Y; Remark: Reserved; SIGNAL_MODEL: ESD_DIODE_0_ESDPSA-0402_KESD531; Status: 商业级; Datasheet: D:\lib_ls\Datasheet\KESD5311N.PDF
FB6 = BEAD: IND FERRITE BEAD, 60 Ohm, ±25%, FB0603/SMT, 3A, 0.04 Ohm, ROHS; Component Name: 60@100MHZ 3A PBY160808T-600Y-N; Manufacturer: CHILISIN; Manufacturer PN: PBY160808T-600Y-N; Option: I; Package type: SMT; Part Number: LFB60031YF2CN1; Part Type: 磁珠; ROHS: Y; Remark: Reserved; Status: 商业级; Datasheet: D:\lib\Datasheet\Inductor-Bead\PBY160808T-600Y-N.pdf
FB129 = BEAD: IND FERRITE BEAD, 60 Ohm, ±25%, FB0402/SMT, 3A, 0.04 Ohm, ROHS; Component Name: 60@100MHZ 3A TAI-TECH(台庆) HCB1005KF-600T30; ID: 131; Manufacturer: TAI-TECH(台庆); Manufacturer PN: HCB1005KF-600T30; Option: I; Package type: SMT; Part Number: LFB60031YF2TT1-GZ; Part Type: 磁珠; ROHS: Y; Remark: Reserved; Status: 商业级; Datasheet: D:\lib_ls\Datasheet\Inductor-Bead\C356960_磁珠_HCB1005KF-600T30.PDF
J6 = 1_25_1x2pin: CNT BOX HEADER, 1.25MM,直插,镀锡,2P,针座连接器; Component Name: CNT BOX HEADER, MX1.25,直插,镀锡,2P,针座连接器; ID: 508; Manufacturer: CJT(长江连接器); Option: I; Package type: DIP; Part Number: J282001X021CJ1-GZ; Part Type: 接插件    PIN HEADER; ROHS: Y; Remark: Reserved; Status: 商业级; Datasheet: D:\lib_ls\Datasheet\connector\28\A1251（1.25mm，2pin，dip）.pdf
J10 = 2_00_2: CNT Dual HEADER,2_00_2X4PIN,Econn/P5D08E-4.0\2.0\3.0-A1,HEAD4X2-79/DIP,2.00mm，Black，Vertical，Unknown ROHS; Component Name: CNT Dual HEADER,2_00_2X4PIN,Econn/P5D08E-4.0\2.0\3.0-A1,HEAD4X2-79/DIP,2.00mm，Black，Vertical，Unknown ROHS; ID: 166; Manufacturer: Econn; Option: I; Part Number: J262002X041EC1; Part Type: 接插件    PIN HEADER; ROHS: /; Remark: Reserved; Status: 商业级; Datasheet: D:\lib_ls\Datasheet\Connector\26\J262002X041EC1.pdf
R51 = R: RESISITOR, 330R Ohm, 5%, R0603/SMT, 1/10W, ROHS; Component Name: 330R 5% R0603 TORCH RC0603-331J-T; ID: 114; Manufacturer: TORCH; Manufacturer PN: RC0603-331J-T; Option: I; Package type: SMT; Part Number: R1103313JC2TO1; Part Type: 电阻; ROHS: Y; Remark: Reserved; Status: 商业级; Datasheet: D:\lib_ls\Datasheet\RC\TORCH-R.pdf
R133-R136 R138 R142 = R_v5: RESISITOR,22R Ohm,5%,R0402/SMT, 1/16W,ROHS; Component Name: 22R 5% R0402 FH  RC-02W220JT; ID: 1,186; Manufacturer: FH(风华); Manufacturer PN: RC-02W220JT; Option: I; Part Number: RJ102202JC2FH1-GZ; Part Type: 电阻; ROHS: Y; Remark: Reserved; SIGNAL_MODEL: R_R0402_22R_5%; Status: 商业级; Datasheet: D:\lib_ls\Datasheet\RC\FH-R.pdf
R140 = R_v5: RESISITOR,22R Ohm,5%,R0402/SMT, 1/16W,ROHS; Component Name: 22R 5% R0402 FH  RC-02W220JT; ID: 1,186; Manufacturer: FH(风华); Manufacturer PN: RC-02W220JT; Option: I; Part Number: RJ102202JC2FH1-GZ; Part Type: 电阻; ROHS: Y; Remark: Reserved; SIGNAL_MODEL: R_R0402_33R_5%_33R_5%; Status: 商业级; Datasheet: D:\lib_ls\Datasheet\RC\FH-R.pdf
R144 = R: RESISITOR, 4.7K Ohm, 5%, R0402/SMT, 1/16W, ROHS; Component Name: 4.7K 5% R0402 FH RC-02W472JT; ID: 1,195; Manufacturer: FH(风华); Manufacturer PN: RC-02W472JT; Option: I; Package type: SMT; Part Number: R1104722JC2FH1-GZ; Part Type: 电阻; ROHS: Y; Remark: Reserved; Status: 商业级; Datasheet: D:\lib_ls\Datasheet\RC\FH-R.pdf
R160 R163 = R_v5: RESISITOR, 0R Ohm, 5%, R0402/SMT, 1/16W, ROHS; Component Name: 0R 5% R0402 FH RC-02000JT; ID: 1,250; Manufacturer: FH(风华); Manufacturer PN: RC-02000JT; Option: I; Package type: SMT; Part Number: R1100002JC2FH1-GZ; Part Type: 电阻; ROHS: Y; Remark: Dummy; Status: 商业级; Datasheet: D:\lib_ls\Datasheet\RC\FH-R.pdf
R55 R57 R59 R61 R161 R162 R191 R195 R198 R202 R203 R218-R220 = R_v5: RESISITOR, 4.7K Ohm, 5%, R0402/SMT, 1/16W, ROHS; Component Name: 4.7K 5% R0402 FH RC-02W472JT; ID: 1,195; Manufacturer: FH(风华); Manufacturer PN: RC-02W472JT; Option: I; Package type: SMT; Part Number: R1104722JC2FH1-GZ; Part Type: 电阻; ROHS: Y; Remark: Reserved; Status: 商业级; Datasheet: D:\lib_ls\Datasheet\RC\FH-R.pdf
R166 R169 R175 R182 = R_v5: RESISITOR, 4.7K Ohm, 5%, R0402/SMT, 1/16W, ROHS; Component Name: 4.7K 5% R0402 FH RC-02W472JT; ID: 1,195; Manufacturer: FH(风华); Manufacturer PN: RC-02W472JT; Option: I; Package type: SMT; Part Number: R1104722JC2FH1-GZ; Part Type: 电阻; ROHS: Y; Remark: Reserved; SIGNAL_MODEL: R_R0402_4.7K_5%_4.7K_5%; Status: 商业级; Datasheet: D:\lib_ls\Datasheet\RC\FH-R.pdf
R47 R49 R72 R74 R112-R127 R131 R132 R167 R172 R174 R176 R187-R190 R192-R194 R196 R197 R199-R201 R204-R210 = R_v5: RESISITOR,22R Ohm,5%,R0402/SMT, 1/16W,ROHS; Component Name: 22R 5% R0402 FH  RC-02W220JT; ID: 1,186; Manufacturer: FH(风华); Manufacturer PN: RC-02W220JT; Option: I; Package type: SMT; Part Number: RJ102202JC2FH1-GZ; Part Type: 电阻; ROHS: Y; Remark: Reserved; Status: 商业级; Datasheet: D:\lib_ls\Datasheet\RC\FH-R.pdf
R170 = R_v5: RESISITOR,22R Ohm,5%,R0402/SMT, 1/16W,ROHS; Component Name: 22R 5% R0402 FH  RC-02W220JT; ID: 1,186; Manufacturer: FH(风华); Manufacturer PN: RC-02W220JT; Option: I; Package type: SMT; Part Number: RJ102202JC2FH1-GZ; Part Type: 电阻; ROHS: Y; Remark: Reserved; SIGNAL_MODEL: R_R0402_33R_5%_33R_5%; Status: 商业级; Datasheet: D:\lib_ls\Datasheet\RC\FH-R.pdf
R171 = R_v5: RESISTOR, 100K Ohm, 1%, R0402/SMT, 1/16W, ROHS; Component Name: 100K 1% R0402 YAGEO RC0402FR-07100KL; ID: 193; Manufacturer: YAGEO; Manufacturer PN: RC0402FR-07100KL; Option: I; Package type: SMT; Part Number: R1110032FC2YG1; Part Type: 电阻; ROHS: Y; Remark: Reserved; Status: 商业级; Datasheet: D:\lib_ls\Datasheet\RC\YAGEO-R.pdf
R173 = R_v5: RESISITOR, 4.7K Ohm, 5%, R0402/SMT, 1/16W, ROHS; Component Name: 4.7K 5% R0402 FH RC-02W472JT; ID: 1,195; Manufacturer: FH(风华); Manufacturer PN: RC-02W472JT; Option: I; Package type: SMT; Part Number: R1104722JC2FH1-GZ; Part Type: 电阻; ROHS: Y; Remark: Dummy; SIGNAL_MODEL: R_R0402_4.7K_5%_4.7K_5%; Status: 商业级; Datasheet: D:\lib_ls\Datasheet\RC\FH-R.pdf
R211 = R_v5: RESISITOR,22R Ohm,5%,R0402/SMT, 1/16W,ROHS; Component Name: 22R 5% R0402 FH  RC-02W220JT; ID: 1,186; Manufacturer: FH(风华); Manufacturer PN: RC-02W220JT; Option: I; Part Number: RJ102202JC2FH1-GZ; Part Type: 电阻; ROHS: Y; Remark: Dummy; Status: 商业级; Datasheet: D:\lib_ls\Datasheet\RC\FH-R.pdf
R213-R215 R217 = R_v5: RESISITOR,22R Ohm,5%,R0402/SMT, 1/16W,ROHS; Component Name: 22R 5% R0402 FH  RC-02W220JT; ID: 1,186; Manufacturer: FH(风华); Manufacturer PN: RC-02W220JT; Option: I; Part Number: RJ102202JC2FH1-GZ; Part Type: 电阻; ROHS: Y; Remark: Reserved; Status: 商业级; Datasheet: D:\lib_ls\Datasheet\RC\FH-R.pdf
SDCARD1 = SDC_8P-3_60: CNT TF SOCKET,9pin/SMT,XUNPU/TF-115-BCP9,14.5x14.75x1.8mm,ROHS; Component Name: CNT TF SOCKET,9pin/SMT,XUNPU/TF-115-BCP9,14.5x14.75x1.8mm,ROHS; ID: 570; Manufacturer: XUNPU(讯普); Option: I; Part Number: J31TF01AX12XP1-GZ; Part Type: 接插件    TF卡座; ROHS: Y; Remark: 自弹式 MicroSD卡(TF卡) 卡座; Status: 商业级; Datasheet: D:\lib_ls\Datasheet\connector\31\TF-115-BCP9.PDF
TP1-TP3 TP5-TP9 = SD_TSTR: PAGE: 5; Remark: Dummy
C12 C14 C17-C21 C37 C39-C41 C51-C53 C67 = C: CAP,MLCC,22UF,16V,10%,C0805/SMT,X5R,ROHS; Component Name: 22UF 16V C0805 SAMSUNG CL21A226MOQNNNE; ID: 567; Manufacturer: SAMSUNG(三星); Manufacturer PN: CL21A226MOQNNNE; Option: I; Package type: SMT; Part Number: C1122645K62SA1-GZ; Part Type: 陶瓷电容; ROHS: Y; Remark: Reserved; Status: 商业级; Datasheet: D:\lib_ls\Datasheet\RC\CL21A226MOQNNNE.PDF
C62 = C: CAP,MLCC,0.01UF,2KV,10%,C1206/SMT,X7R,ROHS; Component Name: 0.01UF 2KV C1206 FH 1206B103K202NT; ID: 504; Manufacturer: FH(风华); Manufacturer PN: 1206B103K202NT; Option: I; Package type: SMT; Part: 0.01UF 2KV  NC; Part Number: C111036XKM2FH1-GZ; Part Type: 陶瓷电容; ROHS: Y; Remark: Reserved; Status: 商业级; Datasheet: D:\lib_ls\Datasheet\RC\FH-C.pdf
CON3 = TYPE_C_0: CNT TYPE C,HRO/TYPE-C-31-M-12,母座 贴片,ROHS; Manufacturer: HRO韩国韩荣; Manufacturer PN: TYPE-C-31-M-12; Remark: https://item.szlcsc.com/177331.html
FB3 = BEAD: IND FERRITE BEAD, 60 Ohm, ±25%, FB0603/SMT, 3A, 0.04 Ohm, ROHS; Component Name: 60@100MHZ 3A PBY160808T-600Y-N; ID: 18; Manufacturer: CHILISIN; Manufacturer PN: PBY160808T-600Y-N; Option: I; Package type: SMT; Part Number: LFB60031YF2CN1; Part Type: 磁珠; ROHS: Y; Remark: Reserved; Status: 商业级; Datasheet: D:\lib_ls\Datasheet\Inductor-Bead\PBY160808T-600Y-N.pdf
R52 = R_v6: RESISITOR, 10K Ohm, 1%, R0402/SMT, 1/16W, ROHS; ASM_COMM: 5010; Component Name: 10K 1% R0402 FH RC-02W1002FT; GREEN_TYPE: 7-HE ŸoûuËØ&šWÃËÅÅÍâ—l¿î; ID: 1,047; MANUFACTURER: FH(风华); Manufacturer PN: RC-02W1002FT; Option: I; PART_NUMBER: R11-0103T12-W08; PART_TYPE: R; Package type: SMT; Part Number: R1110022FC2FH1; Part Type: 电阻; REMARK: Reserved; ROHS: Y; Status: 商业级; Datasheet: D:\lib_ls\Datasheet\RC\FH-R.pdf
R53 = R: RESISTOR, 100K Ohm, 1%, R0402/SMT, 1/16W, ROHS; Component Name: 100K 1% R0402 YAGEO RC0402FR-07100KL; ID: 193; Manufacturer: YAGEO; Manufacturer PN: RC0402FR-07100KL; Option: I; Package type: SMT; Part Number: R1110032FC2YG1; Part Type: 电阻; ROHS: Y; Remark: Reserved; Status: 商业级; Datasheet: D:\lib_ls\Datasheet\RC\YAGEO-R.pdf
R54 R56 R128 R130 R165 = R: RESISITOR, 0R Ohm, 5%, R0402/SMT, 1/16W, ROHS; Component Name: 0R 5% R0402 FH RC-02000JT; ID: 1,250; Manufacturer: FH(风华); Manufacturer PN: RC-02000JT; Option: I; Package type: SMT; Part Number: R1100002JC2FH1-GZ; Part Type: 电阻; ROHS: Y; Remark: Reserved; Status: 商业级; Datasheet: D:\lib_ls\Datasheet\RC\FH-R.pdf
R62 R67 = R: RESISITOR, 5.1K Ohm, 1%, R0402/SMT, 1/16W, ROHS; Component Name: 5.1K 5% R0402 FH RC-02K5101FT; ID: 1,221; Manufacturer: FH(风华); Manufacturer PN: RC-02K5101FT; Option: I; Package type: SMT; Part: 0R 5%; Part Number: R1105122JC2FH1-GZ; Part Type: 电阻; ROHS: Y; Remark: Reserved; Status: 商业级; Datasheet: D:\lib_ls\Datasheet\RC\FH-R.pdf
R150 = R: RESISITOR, 1M Ohm, 5%, R0603/SMT, 1/10W, ROHS; Component Name: 1M 5% R0603 TORCH RC0603-105J-T; ID: 29; Manufacturer: TORCH; Manufacturer PN: RC0603-105J-T; Option: I; Package type: SMT; Part Number: R1101053JC2TO1; Part Type: 电阻; ROHS: Y; Remark: Reserved; Status: 商业级; Datasheet: D:\lib_ls\Datasheet\RC\TORCH-R.pdf
U3 = SGM4553: IC Others,杭州瑞盟/MS4553S,SOT23-8/SMT,dual bidirectional I2C Bus voltage-level translator,ROHS; ID: 1,113; Manufacturer: 杭州瑞盟; Option: I; Part Number: UZ1MS4553S2RM1-GZ; Part Type: IC/Others; ROHS: Y; Remark: Reserved; Status: 工业级; Datasheet: D:\lib_ls\Datasheet\MS4553S.pdf
U4 = CH340E_0: IC Others, 江苏沁恒/CH340K, ESSOP10/SMT, USB 转串口芯片CH340K, ROHS; Component Name: 江苏沁恒CH340K; Manufacturer: 江苏沁恒股份有限公司; Option: I; Package type: SMT; Part Type: IC/Others; ROHS: Y; Remark: Reserved; Reserved: TOP-SIDE MARKING:CH340K; Status: 商业级; Datasheet: Z:\lib\Datasheet\IC\CH340E.pdf
C6 C10 = C: CAP,MLCC,0.1UF,16V,10%,C0402/SMT,X7R,ROHS; Component Name: 0.1UF 16V C0402 YAGEO CC0402KRX7R7BB104; Manufacturer: YAGEO; Manufacturer PN: CC0402KRX7R7BB104; Option: I; Package type: SMT; Part Number: C111042XK62YG1; Part Type: 陶瓷电容; ROHS: Y; Remark: Reserved; SIGNAL_MODEL: C_C0402_0.1UF_16V_0.1UF_16V; Status: 商业级; Datasheet: Z:\lib\Datasheet\RC\YAGEO-C.pdf
C38 C42-C44 = C: CAP,MLCC,0.1UF,16V,10%,C0402/SMT,X7R,ROHS; Component Name: 0.1UF 16V C0402 YAGEO CC0402KRX7R7BB104; Manufacturer: YAGEO; Manufacturer PN: CC0402KRX7R7BB104; Option: I; Package type: SMT; Part Number: C111042XK62YG1; Part Type: 陶瓷电容; ROHS: Y; Remark: Reserved; Status: 商业级; Datasheet: Z:\lib\Datasheet\RC\YAGEO-C.pdf
D38-D41 = DIODE_SCHOTTKY_AC: DIODE, SOD923/SMT, ,VR = 30V,IF = 200mA, ROHS; Component Name: TECH PUBLIC(台舟) RB521CS-30; ID: 161; Manufacturer: TECH PUBLIC(台舟); Option: I; Package type: SMT; Part Number: D11RB521CS30J1-GZ; Part Type: 二极管; ROHS: Y; Remark: Reserved; Status: 商业级; Datasheet: D:\lib_ls\Datasheet\Diodes-Transistor\RB521CS-30.pdf
J1-J4 = 2_00_1X6PIN: CNT BOX HEADER,2_00_1X6PIN,JST/B6B-PH-K(LF)(SN),6pin/DIP,2.00mm,Ivory,Horizontal,ROHS; Component Name: CNT BOX HEADER,2_00_1X6PIN,JST/B6B-PH-K(LF)(SN),6pin/DIP,2.00mm,Ivory,Horizontal,ROHS; ID: 572; Manufacturer: JST; Option: I; Part Number: J262001X062JS1-GZ; Part Type: 接插件    PIN HEADER; ROHS: /; Remark: 1x6P 间距:2mm 直插 PH 象牙色; Status: 商业级; Datasheet: D:\lib_ls\Datasheet\Connector\26\B6B-PH-K(LF)(SN).PDF
J5 = 2_54_1X3PIN: CNT Single HEADER,2_54_1X3PIN,JILN/12251103CNG0S115001,3pin /DIP,2.54mm,Black,Vertical,Through,ROHS; Component Name: CNT Single HEADER,2_54_1X3PIN,JILN/12251103CNG0S115001,3pin /DIP,2.54mm,Black,Vertical,Through,ROHS; ID: 569; Manufacturer: JILN(锦凌); Option: I; Part Number: J262541X031JL1-GZ; Part Type: 接插件    PIN HEADER; Remark: Dummy; Status: 商业级; Datasheet: D:\lib_ls\Datasheet\connector\26\12251103CNG0S115001.PDF
J9 = 2_54_2X20PIN: CNT Dual HEADER,2_54_2x20PIN,TB/P40,DIP,2.54mm,Colour,Horiz,ROHS; Component Name: CNT Dual HEADER,2_54_2x20PIN,TB/P40,DIP,2.54mm,Colour,Horiz,ROHS; ID: 567; Manufacturer: TB(市购); Manufacturer PN: P40; Option: I; Part Number: J262542X20FTB1-GZ; Part Type: 接插件    PIN HEADER; ROHS: Y; Remark: 间距:2.54mm 2x20P 直插 彩色 铜针 镀金 https://item.taobao.com/item.htm?abbucket=6&id=663421091701&ns=1&skuId=4954861015125&spm=a21n57.1.0.0.21a4523cqzjw93; Status: 商业级; Datasheet: D:\lib_ls\Datasheet\Connector\26\12251220ANG0S115001.pdf
C22 C59 = C: CAP,MLCC,0.1UF,50V,10%,C0603/SMT,X7R,ROHS; Component Name: 0.1UF 50V C0603 YAGEO C0603KRX7R9BB104; ID: 24; Manufacturer: YAGEO; Manufacturer PN: C0603KRX7R9BB104; Option: I; Package type: SMT; Part: 0.1UF 16V; Part Number: C111043XKA2YG1; Part Type: 陶瓷电容; ROHS: Y; Remark: Reserved; Status: 商业级; Datasheet: D:\lib_ls\Datasheet\RC\YAGEO-C.pdf
C55 = C: CAP,MLCC,1UF,25V,15%,C0603/SMT,X7R,ROHS; Component Name: 1UF 25V C0603 FH 0603B105K250NT; ID: 557; Manufacturer: FH(风华); Manufacturer PN: 0603B105K250NT; Option: I; Package type: SMT; Part Type: 陶瓷电容; ROHS: Y; Remark: C215803; Status: 商业级; Datasheet: Z:\lib\Datasheet\RC\YAGEO-C.pdf
C56 = C: CAP,MLCC,0.1UF,16V,10%,C0402/SMT,X7R,ROHS; Component Name: 0.1UF 16V C0402 YAGEO CC0402KRX7R7BB104; ID: 22; Manufacturer: YAGEO; Manufacturer PN: CC0402KRX7R7BB104; Option: I; Package type: SMT; Part Number: C111042XK62YG1; Part Type: 陶瓷电容; ROHS: Y; Remark: Dummy; Status: 商业级; Datasheet: D:\lib_ls\Datasheet\RC\YAGEO-C.pdf
C58 = C: CAP,MLCC,0.1UF,50V,10%,C0603/SMT,X7R,ROHS; Component Name: 0.1UF 50V C0603 YAGEO C0603KRX7R9BB104; ID: 24; Manufacturer: YAGEO; Manufacturer PN: C0603KRX7R9BB104; Option: I; Package type: SMT; Part Number: C111043XKA2YG1; Part Type: 陶瓷电容; ROHS: Y; Remark: Reserved; Status: 商业级; Datasheet: D:\lib_ls\Datasheet\RC\YAGEO-C.pdf
CON4 = J03DC6D0011EC1: CNT DC adaptor,3pin/DIP,9×11×14mm,Φ2.0，Black, Horizon,ROHS; Component Name: CNT DC adaptor,3pin/DIP,9×11×14mm,Φ2.0，Black, Horizon,ROHS; ID: 574; Manufacturer: XUNPU(讯普); Option: I; Package type: DIP; Part: DC6D-005A-1B2; Part Number: J03DC005A21XP1-GZ; Part Type: 接插件    Power jack; ROHS: /; Remark: Reserved; Status: 商业级; Temperature: Ta=-25 to +70; Datasheet: D:\lib_ls\Datasheet\Connector\03\DC-005-A200.PDF
D37 = TL431_0: IC REFERENCE,TI/TL431BIDBZR,SOT23-3/SMT,0.5%,PRECISION PROGRAMMABLE REFERENCE,ROHS; Manufacturer: TI; Manufacturer PN: TL431BIDBZR; Option: I; Package type: SMT; ROHS: Y; Remark: Reserved
EC1 = CT: CAP,钽电容,100UF,10V,20%,TC3528-21/SMT,ROHS; Component Name: 22UF 16V TC3528-21 KEMET T491B226K016AT; ID: 194; Manufacturer: Sunlord(顺络); Manufacturer PN: TC212B107M010B; Option: I; Package type: SMT; Part Type: 钽电容; ROHS: Y; Remark: Reserved; Status: 商业级
F1 = 0451005: FUSE,2PIN/1206 ,VMAX = 6V, I(HOLD) = 5A, ROHS; Component Name: 保险丝,LittelFuse,0451005; ID: 23; Manufacturer: BNstar(比诺星); Manufacturer PN: SMD1206-500-6V; Option: I; Package type: SMT; Part Type: 保险丝; ROHS: Y; Remark: Reserved; Status: 商业级; Datasheet: D:\lib_ls\Datasheet\Z\0451005.pdf
FB4 FB7 = BEAD: IND FERRITE BEAD, 60 Ohm, ±25%, FB0603/SMT, 3A, 0.04 Ohm, ROHS; Component Name: 60@100MHZ 3A PBY160808T-600Y-N; Manufacturer: CHILISIN; Manufacturer PN: PBY160808T-600Y-N; Option: I; Package type: SMT; Part Number: LFB60031YF2CN1; Part Type: 磁珠; ROHS: Y; Remark: Dummy; Status: 商业级; Datasheet: D:\lib\Datasheet\Inductor-Bead\PBY160808T-600Y-N.pdf
J7 = 1_25_1x2pin: CNT BOX HEADER,2_54_1X2PIN, HX/ZX-XH2.54-2PZZA,DIP,2.54MM,White,Vertical,ROHS; Component Name: CNT BOX HEADER,2_54_1X2PIN, HX/ZX-XH2.54-2PZZA,DIP,2.54MM,White,Vertical,ROHS; ID: 571; Manufacturer: Megastar(兆星); Manufacturer PN: ZX-XH2.54-2PZZ; Option: I; Part Number: J26XH2542PZZX1-GZ; Part Type: 接插件    PIN HEADER; ROHS: /; Remark: Dummy; Status: 商业级; Datasheet: D:\lib_ls\Datasheet\Connector\26\ZX-XH2.54-2PZZ.pdf
MH1-MH4 = HOLE_3: Option: NC; Remark: Dummy
Q1 = SI7232DN-T1-GE3: IC MOSFET,Sinopower(大中)/SM3429BSQAC-TRG,DFN-8-EP/SMT,Dual P-MOSFET,-20V (D-S),-19A,ROHS; Component Name: Si7232DN-T1-GE3; ID: 1,107; Manufacturer: Sinopower(大中); Option: I; Part Number: US1SM3429D2VY1-GZ; Part Type: IC/P-Channel; ROHS: Y; Remark: Reserved; Status: 商业级; Datasheet: D:\lib_ls\Datasheet\SI7232DN-T1-GE3.pdf
Q3 Q4 = 2N7002LT1G: IC MOSFET, LRC/L2N7002LT1G, SOT23-3/SMT, 60 V 115 mA N-Channel SOT-23, ROHS; Component Name: LRC    L2N7002LT1G; ID: 253; Manufacturer: LRC; Option: I; Package type: SMT; Part Number: US12N700232QT1; Part Type: IC/N-Channel; ROHS: Y; Remark: Reserved; Status: 商业级; Temperature: Tj=-55 to +150; Datasheet: D:\lib_ls\Datasheet\IC\L2N7002LT1G.pdf
R71 = R: RESISTOR, 300R Ohm, 5%, R0805/SMT, 1/8W, ROHS; Component Name: 300R 5% R0805 FH RS-05K3000FT; ID: 1,270; Manufacturer: FH(风华); Manufacturer PN: RS-05K3000FT; Option: I; Package type: SMT; Part Number: R1103015JC2FH1-GZ; Part Type: 电阻; ROHS: Y; Remark: Reserved; Status: 商业级; Datasheet: D:\lib_ls\Datasheet\RC\FH-R.pdf
R73 = R_v5: RESISITOR, 10K Ohm, 1%, R0402/SMT, 1/16W, ROHS; Component Name: 10K 1% R0402 FH RC-02W1002FT; ID: 1,170; Manufacturer: FH(风华); Manufacturer PN: RC-02W1002FT; Option: I; Part Number: R1110022FC2FH1-GZ; Part Type: 电阻; ROHS: Y; Remark: Reserved; Status: 商业级; Datasheet: D:\lib_ls\Datasheet\RC\FH-R.pdf
R78 = R: RESISTOR, 100K Ohm, 1%, R0402/SMT, 1/16W, ROHS; Component Name: 100K 1% R0402 YAGEO RC0402FR-07100KL; ID: 193; Manufacturer: YAGEO; Manufacturer PN: RC0402FR-07100KL; Option: I; Package type: SMT; Part Number: R1110032FC2YG1; Part Type: 电阻; ROHS: Y; Remark: Dummy; Status: 商业级; Datasheet: D:\lib_ls\Datasheet\RC\YAGEO-R.pdf
R79 = R_v5: RESISITOR, 4.7K Ohm, 5%, R0402/SMT, 1/16W, ROHS; Component Name: 4.7K 5% R0402 FH RC-02W472JT; ID: 1,195; Manufacturer: FH(风华); Manufacturer PN: RC-02W472JT; Option: I; Part Number: R1104722JC2FH1-GZ; Part Type: 电阻; ROHS: Y; Status: 商业级; Datasheet: D:\lib_ls\Datasheet\RC\FH-R.pdf
R111 R158 = R: RESISITOR, 0R Ohm, 5%, R0402/SMT, 1/16W, ROHS; Component Name: 0R 5% R0402 YAGEO RC0402JR-070RL; Manufacturer: YAGEO; Manufacturer PN: RC0402JR-070RL; Option: I; Package type: SMT; Part Number: R1100002JC2YG1; Part Type: 电阻; ROHS: Y; Remark: Dummy; Status: 商业级; Datasheet: D:\lib\Datasheet\RC\YAGEO-R.pdf
R147 = R_v5: RESISITOR, 1.65K Ohm, 1%, R0402/SMT, 1/16W, ROHS; Component Name: 1.65K 1% R0402 FH RC-02W1651FT; ID: 1,233; Manufacturer: FH(风华); Manufacturer PN: RC-02W1651FT; Option: I; Part Number: R1116512FC2FH1-GZ; Part Type: 电阻; ROHS: Y; Remark: Reserved; Status: 商业级; Datasheet: D:\lib_ls\Datasheet\RC\FH-R.pdf
R148 R221 = R: RESISTOR,6.8K Ohm,1%,R0402/SMT, 1/16W,ROHS; Component Name: 6.8K 1% R0603 FH RC-02W6801FT; ID: 1,274; Manufacturer: FH(风华); Manufacturer PN: RC-02W6801FT; Option: I; Package type: SMT; Part Number: R1168013FC2FH1-GZ; Part Type: 电阻; ROHS: Y; Remark: Reserved; Status: 工业级; Datasheet: D:\lib_ls\Datasheet\RC\FH-R.pdf
R149 = R_v5: RESISTOR,2.32K Ohm,1%,1/16W,R0402/SMT,ROHS; Component Name: 2.32K 1% R0402 FH RC-02W2321FT; ID: 1,269; Manufacturer: FH(风华); Manufacturer PN: RC-02W2321FT; Option: I; Part Number: R1123212FC2FH1-GZ; Part Type: 电阻; ROHS: Y; Remark: C321383; Status: 工业级; Datasheet: D:\lib_ls\Datasheet\RC\FH-R.pdf
R151 = R_v5: RESISITOR, 1K Ohm, 1%, R0402/SMT, 1/16W, ROHS; Component Name: 1K 1% R0402 YAGEO RC0402FR-071KL; ID: 188; Manufacturer: YAGEO; Manufacturer PN: RC0402FR-071KL; Option: I; Part Number: R1110012FC2YG1; Part Type: 电阻; ROHS: Y; Remark: Reserved; Status: 商业级; Datasheet: D:\lib_ls\Datasheet\RC\YAGEO-R.pdf
R152 = R_v5: RESISITOR, 2.2R Ohm, 5%, R0805/SMT, 1/8W, ROHS; Component Name: 2.2R 5% R0603 FH RS-03L2R20FT; ID: 1,268; Manufacturer: FH(风华); Manufacturer PN: RS-03L2R20FT; Option: I; Part Type: 电阻; ROHS: Y; Remark: C286623; Status: 商业级; Datasheet: D:\lib_ls\Datasheet\RC\FH-R.pdf
R153 = R: RESISITOR, 4.7K Ohm, 5%, R0402/SMT, 1/16W, ROHS; Component Name: 4.7K 5% R0402 YAGEO RC0402JR-074K7L; Manufacturer: FH(风华); Manufacturer PN: RC-02W472JT; Option: I; Package type: SMT; Part Type: 电阻; ROHS: Y; Remark: Reserved; Status: U; Datasheet: Z:\lib\Datasheet\RC\YAGEO-R.pdf
R154 R159 = R: RESISITOR, 6.2K Ohm, 1%, R0402/SMT, 1/16W, ROHS; Component Name: 6.2K 1% R0402 YAGEO RC0402FR-076K2L; ID: 1,295; Manufacturer: YAGEO; Manufacturer PN: RC0402FR-076K2L; Option: I; Package type: SMT; Part Number: R1106222FC2YG1-GZ; Part Type: 电阻; ROHS: Y; Remark: Reserved; Status: 商业级; Datasheet: D:\lib_ls\Datasheet\RC\YAGEO-R.pdf
R155 = R: RESISITOR, 4.7K Ohm, 5%, R0402/SMT, 1/16W, ROHS; Component Name: 4.7K 5% R0402 YAGEO RC0402JR-074K7L; Manufacturer: FH(风华); Manufacturer PN: RC-02W472JT; Option: I; Package type: SMT; Part Type: 电阻; ROHS: Y; Remark: Dummy; Status: U; Datasheet: Z:\lib\Datasheet\RC\YAGEO-R.pdf
R156 = R: RESISITOR, 17.8K Ohm, 1%, R0402/SMT, 1/16W, ROHS; Component Name: 17.8K 1% R0402 FH RC-02W1782FT; ID: 1,177; Manufacturer: FH(风华); Manufacturer PN: RC-02W1782FT; Option: I; Package type: SMT; Part Number: R1117822FC2FH1-GZ; Part Type: 电阻; ROHS: Y; Remark: Reserved; Status: 商业级; Datasheet: D:\lib_ls\Datasheet\RC\FH-R.pdf
U8 = SY6280: IC LOAD SWITCH,SILERGY(矽力杰)/SY6280AAC,SOT23-5/SMT,Ultra-Low On-Resistance,2A,Soft Start,2.4V-5.5V,ROHS; Component Name: SY6280AAC; ID: 1,084; Manufacturer: SILERGY(矽力杰); Manufacturer PN: SY6280AAC; Option: I; Package type: SMT; Part Number: UZ1SY6280H2SY1-GZ; Part Type: IC/Others; ROHS: Y; Remark: Reserved; Status: 工业级; Datasheet: D:\lib_ls\Datasheet\SY6280AAC.pdf

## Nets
GND: C6.2 C10.2 C12.2 C13.2 C14.1 C15.1 C16.2 C17.2 C18.1 C19.2 C20.2 C21.2 C37.2 C38.2 C39.2 C40.2 C41.2 C42.2 C43.2 C44.2 C45.2 C48.2 C49.2 C50.2 C51.2 C52.1 C53.2 C54.2 C55.2 C56.2 C57.2 C58.2 C59.2 C61.2 C62.1 C67.2 C81.1 CON3.A1(GND1) CON3.A12(GND2) CON4.2(VDD) D16.2 D18.2 D24.1 D25.1 D26.1 D27.1 D28.1 D29.1 D30.1 D31.1 D32.1 D33.1 D34.1 D35.1 D36.1 D37.3(ANODE) EC1.2 J1.2 J2.2 J3.2 J4.2 J5.1 J6.2 J7.2 J9.2 J9.6 J9.22 J9.28 J10.7 Q3.2(SOURCE) Q4.2(SOURCE) R53.1 R62.2 R67.2 R71.1 R111.1 R147.1 R148.1 R150.2 R154.2 R158.1 R159.1 R160.2 R163.2 R171.1 SDCARD1.6(VSS) SDCARD1.11(GND) SDCARD1.12(GND) SDCARD1.13(GND) SDCARD1.14(GND) TP3.1 U2.11 U2.12 U2.19 U2.29 U2.58 U2.73 U2.82 U2.83 U2.84 U2.85 U2.86 U2.94 U2.103 U2.112 U2.119 U2.137 U3.5(GND) U4.3(GND) U4.11(E_GND) U8.2(GND) ; also on sheet 1 2 3 4 13
GND_EARTH_L: C62.2 CON3.S1(SHIELD1) CON3.S2(SHIELD2) CON3.S3(SHIELD3) CON3.S4(SHIELD4) MH3.1 R150.1
GND_EARTH_R: MH2.1 MH4.1 ; also on sheet 3 4
P3V3: C6.1 C37.1 C38.1 C39.1 C40.1 C41.1 C42.1 C43.1 C44.1 C48.1 C67.1 FB6.2 J1.1 J2.1 J3.1 J4.1 J9.1 R52.2 R55.1 R57.1 R59.1 R61.1 R144.2 R161.2 R162.2 R166.1 R169.1 R173.1 R175.1 R182.1 R191.1 R195.1 R198.1 R202.1 R203.1 R218.1 R219.1 R220.1 U3.8(VCCA) ; also on sheet 1 2 3 4 13
P3V3_IN: FB129.2 U2.75 U2.76 U2.77 U2.78 U2.79 U2.80 U2.81 ; also on sheet 2
P5V: C10.1 C12.1 C16.1 C20.1 C21.1 C49.1 C51.1 EC1.1 FB4.2 FB7.2 J9.27 Q1.5(D2) R71.2 TP2.1 U8.1(OUT) ; also on sheet 1 2 3 4
P5VSB: C17.1 C19.1 C59.1 F1.2 FB4.1 Q1.8(D1) R78.2 R149.1 R151.2 R152.2 R156.2 TP1.1
VBAT: C15.2 R51.2 U2.74
AI0: J9.29 ; also on sheet 4
AI1: J9.31 ; also on sheet 4
AI2: J9.33 ; also on sheet 4
AI3: J9.35 ; also on sheet 4
AI4: J9.30 ; also on sheet 4
AI5: J9.36 ; also on sheet 4
AI6: J9.34 ; also on sheet 4
AI7: J9.32 ; also on sheet 4
CAN0_RX: J4.4 R113.1
CAN0_TX: J4.3 R112.1
CAN1_RX: J4.6 R115.1
CAN1_TX: J4.5 R114.1
CAN2_RX: J3.4 R117.1
CAN2_TX: J3.3 R116.1
CAN3_RX: J3.6 R119.1
CAN3_TX: J3.5 R118.1
CARD_DET: D36.2 R142.2 SDCARD1.9(CARD_DETECTION)
CH340_P5V: C13.1 C14.2 C52.2 C54.1 FB3.1 U3.1(VCCB) U4.7(VCC)
CH_RXD: R56.1 U4.9(RXD)
CH_TXD: R54.1 U4.8(TXD)
CHRXD: R128.1 U3.7(A1)
CHTXD: R130.1 U3.6(A2)
CPU_ADC_IN0: U2.102 ; also on sheet 4
CPU_ADC_IN1: U2.100 ; also on sheet 4
CPU_ADC_IN2: U2.98 ; also on sheet 4
CPU_ADC_IN3: U2.96 ; also on sheet 4
CPU_ADC_IN4: U2.101 ; also on sheet 4
CPU_ADC_IN5: U2.99 ; also on sheet 4
CPU_ADC_IN6: U2.97 ; also on sheet 4
CPU_ADC_IN7: U2.95 ; also on sheet 4
CPU_CAN0_RX: R113.2 U2.4
CPU_CAN0_TX: R112.2 U2.3
CPU_CAN1_RX: R115.2 U2.10
CPU_CAN1_TX: R114.2 U2.9
CPU_CAN2_RX: R117.2 U2.6
CPU_CAN2_TX: R116.2 U2.5
CPU_CAN3_RX: R119.2 U2.8
CPU_CAN3_TX: R118.2 U2.7
CPU_DOTESTN: R160.1 R161.1 U2.93
CPU_GMAC1_RXCLK: R193.2 U2.136
CPU_GMAC1_TXCLK_I: R47.2 U2.135
CPU_GMAC1_TXCLK_O: R49.2 U2.134
CPU_I2C0_SCL: R203.2 R204.2 U2.133
CPU_I2C0_SDA: R201.2 R202.2 U2.132
CPU_I2C1_SCL: R206.2 U2.121 ; also on sheet 1
CPU_I2C1_SDA: R205.2 U2.120 ; also on sheet 1
CPU_I2C2_SCL: R55.2 R207.2 U2.125
CPU_I2C2_SDA: R57.2 R208.2 U2.124
CPU_I2C3_SCL: R59.2 R209.2 U2.123
CPU_I2C3_SDA: R61.2 R210.2 U2.122
CPU_I2S_BCLK: J9.21 U2.118
CPU_I2S_DI: J9.23 U2.115
CPU_I2S_DO: J9.24 U2.116
CPU_I2S_LR: J9.26 U2.114
CPU_I2S_MCLK: J9.25 U2.117
CPU_JTAG_SEL: R162.1 R163.1 U2.88
CPU_JTAG_TCK: R170.1 U2.91
CPU_JTAG_TDI: R174.2 U2.89
CPU_JTAG_TDO: R176.1 U2.87
CPU_JTAG_TMS: R167.1 U2.92
CPU_JTAG_TRST: R172.1 U2.90
CPU_LCD_CLK: U2.33 ; also on sheet 1
CPU_LCD_DATA0: U2.34 ; also on sheet 1
CPU_LCD_DATA1: U2.35 ; also on sheet 1
CPU_LCD_DATA2: U2.36 ; also on sheet 1
CPU_LCD_DATA3: U2.37 ; also on sheet 1
CPU_LCD_DATA4: U2.38 ; also on sheet 1
CPU_LCD_DATA5: U2.39 ; also on sheet 1
CPU_LCD_DATA6: U2.40 ; also on sheet 1
CPU_LCD_DATA7: U2.41 ; also on sheet 1
CPU_LCD_DATA8: U2.42 ; also on sheet 1
CPU_LCD_DATA9: U2.43 ; also on sheet 1
CPU_LCD_DATA10: U2.44 ; also on sheet 1
CPU_LCD_DATA11: U2.45 ; also on sheet 1
CPU_LCD_DATA12: U2.46 ; also on sheet 1
CPU_LCD_DATA13: U2.47 ; also on sheet 1
CPU_LCD_DATA14: U2.48 ; also on sheet 1
CPU_LCD_DATA15: U2.49 ; also on sheet 1
CPU_LCD_DATA16: U2.50 ; also on sheet 1
CPU_LCD_DATA17: U2.51 ; also on sheet 1
CPU_LCD_DATA18: U2.52 ; also on sheet 1
CPU_LCD_DATA19: U2.53 ; also on sheet 1
CPU_LCD_DATA20: U2.54 ; also on sheet 1
CPU_LCD_DATA21: U2.55 ; also on sheet 1
CPU_LCD_DATA22: U2.56 ; also on sheet 1
CPU_LCD_DATA23: U2.57 ; also on sheet 1
CPU_LCD_EN: U2.32 ; also on sheet 1
CPU_LCD_HSYNC: U2.31 ; also on sheet 1
CPU_LCD_VSYNC: U2.30 ; also on sheet 1
CPU_SDIO1_CLK: R136.1 U2.18
CPU_SDIO1_CMD: R135.1 U2.17
CPU_SDIO1_DATA0: R138.1 U2.16
CPU_SDIO1_DATA1: R140.1 U2.15
CPU_SDIO1_DATA2: R133.1 U2.14
CPU_SDIO1_DATA3: R134.1 U2.13
CPU_SPI0_CLK: R215.2 U2.69
CPU_SPI0_CSN: R213.1 U2.70
CPU_SPI0_MISO: R214.1 U2.68
CPU_SPI0_MOSI: R217.2 U2.67
CPU_SPI1_CLK: R190.2 U2.66
CPU_SPI1_CSN: R187.2 R219.2 U2.64
CPU_SPI1_MISO: R189.2 U2.65
CPU_SPI1_MOSI: R188.2 U2.63
CPU_SPI2_CLK: R127.2 U2.61 ; also on sheet 1
CPU_SPI2_CSN: R124.2 R220.2 U2.59 ; also on sheet 1
CPU_SPI2_MISO: R126.2 U2.62 ; also on sheet 1
CPU_SPI2_MOSI: R125.2 U2.60 ; also on sheet 1
CPU_TIM1_CH1: R142.1 R144.1 U2.28
CPU_TIM1_CH1N: U2.27 ; also on sheet 1
CPU_TIM1_CH2: U2.24 ; also on sheet 1
CPU_TIM1_CH2N: U2.23 ; also on sheet 13
CPU_TIM1_CH3: U2.26 ; also on sheet 13
CPU_TIM1_CH3N: R120.2 U2.25
CPU_TIM2_CH1: R121.2 U2.22
CPU_TIM2_CH2: R122.2 U2.21
CPU_TIM2_CH3: R123.2 U2.20
CPU_UART0_RXD: R130.2 R131.2 U2.1
CPU_UART0_TXD: R128.2 R132.2 U2.2
CPU_UART1_RXD: R192.2 U2.128
CPU_UART1_TXD: R194.2 U2.129
CPU_UART2_RXD: R196.2 U2.126
CPU_UART2_TXD: R197.2 U2.127
CPU_UART3_RXD: R199.2 U2.130
CPU_UART3_TXD: R200.2 U2.131
CPU_USB0_DM: U2.110 ; also on sheet 3
CPU_USB0_DP: U2.111 ; also on sheet 3
CPU_USB0_DRVBUS: U2.105 ; also on sheet 3
CPU_USB0_ID: U2.107 ; also on sheet 3
CPU_USB1_DM: U2.108 ; also on sheet 3
CPU_USB1_DP: U2.109 ; also on sheet 3
CPU_USB1_OC: U2.106 ; also on sheet 3
DCIN_DET: CON4.3(GND) R165.1
EJTAG_TCK: R169.2 R170.2 TP6.1
EJTAG_TDI: R174.1 R175.2 TP8.1
EJTAG_TDO: R176.2 R182.2 TP9.1
EJTAG_TMS: R166.2 R167.2 TP5.1
EJTAG_TRST: R171.2 R172.2 R173.2 TP7.1
GMAC1_RXCLK: J9.5 R193.1
GMAC1_TXCLK_I: J9.4 R47.1
GMAC1_TXCLK_O: J9.3 R49.1
I2C0_SCL: J9.13 R204.1
I2C0_SDA: J9.14 R201.1
I2C1_SCL: J9.15 R206.1
I2C1_SDA: J9.16 R205.1
I2C2_SCL: J9.17 R207.1
I2C2_SDA: J9.18 R208.1
I2C3_SCL: J9.19 R209.1
I2C3_SDA: J9.20 R210.1
MB_PWREN: U2.113 ; also on sheet 2
MRESET#: R211.1 U2.71 ; also on sheet 13
P0_MDIO0+: U2.138 ; also on sheet 4
P0_MDIO0-: U2.139 ; also on sheet 4
P0_MDIO1+: U2.140 ; also on sheet 4
P0_MDIO1-: U2.141 ; also on sheet 4
P0_MDIO2+: U2.142 ; also on sheet 4
P0_MDIO2-: U2.143 ; also on sheet 4
P0_MDIO3+: U2.144 ; also on sheet 4
P0_MDIO3-: U2.145 ; also on sheet 4
PHY0_LED0: U2.148 ; also on sheet 4
PHY0_LED1: U2.147 ; also on sheet 4
PHY0_LED2: U2.146 ; also on sheet 4
PLTRESETN: U2.72 ; also on sheet 1
PWM0: J2.6 R120.1
PWM1: J2.5 R121.1
PWM2: J2.4 R122.1
PWM3: J2.3 R123.1
SDIO1_CLK: D33.2 R136.2 SDCARD1.5(CLK)
SDIO1_CMD: D32.2 R135.2 SDCARD1.3(CMD)
SDIO1_DATA0: D34.2 R138.2 SDCARD1.7(DAT0)
SDIO1_DATA1: D35.2 R140.2 SDCARD1.8(DAT1)
SDIO1_DATA2: D30.2 R133.2 SDCARD1.1(DAT2)
SDIO1_DATA3: D31.2 R134.2 SDCARD1.2(CD/DAT3)
SPI0_CLK: D26.2 J10.6 R215.1
SPI0_CSN: D24.2 J10.1 R213.2
SPI0_MISO: D25.2 J10.3 R214.2
SPI0_MOSI: D27.2 J10.8 R217.1
SPI1_CLK: J9.40 R190.1
SPI1_CSN: J9.37 R187.1
SPI1_MISO: J9.39 R189.1
SPI1_MOSI: J9.38 R188.1
SPI2_CLK: J1.6 R127.1
SPI2_CSN: J1.3 R124.1
SPI2_MISO: J1.5 R126.1
SPI2_MOSI: J1.4 R125.1
UART0_RXD: D28.2 D38.A(ANODE) R131.1 R218.2
UART0_TXD: D29.2 J5.2 R132.1
UART1_RXD: D39.A(ANODE) R191.2 R192.1
UART1_TXD: J9.7 R194.1
UART1RXD: D39.C(CATHODE) J9.8
UART2_RXD: D40.A(ANODE) R195.2 R196.1
UART2_TXD: J9.9 R197.1
UART2RXD: D40.C(CATHODE) J9.10
UART3_RXD: D41.A(ANODE) R198.2 R199.1
UART3_TXD: J9.11 R200.1
UART3RXD: D41.C(CATHODE) J9.12
USB_DN: CON3.A7(DN1) CON3.B7(DN2) D18.1 U4.2(UD-)
USB_DP: CON3.A6(DP1) CON3.B6(DP2) D16.1 U4.1(UD+)
USB_VBUS: C18.2 C53.1 C57.1 CON3.A4(VBUS1) CON3.A9(VBUS2) FB3.2 FB7.1 R153.2 R155.2 U8.5(IN)
USB_VBUSIN: U2.104 ; also on sheet 3
N21733684: CON4.1(GND) F1.1 J7.1
N21788378: C50.1 U4.10(V3)
N21805568: J6.1 R51.1
N21821121: R56.2 U3.2(B1)
N21821123: R54.2 U3.3(B2)
N21821131: R52.1 R53.2 U3.4(OE)
N21821540: CON3.A5(CC1) R62.1
N21821542: CON3.B5(CC2) R67.1
N21889419: C56.1 Q3.3(DRAIN) R153.1 U8.4(EN)
N21889500: C61.1 Q3.1(GATE) R155.1 R156.1 R159.2 R165.2
N21934934: C45.1 FB6.1 SDCARD1.4(VDD)
N21952179: C81.2 FB129.1 J10.2
N21952209: J10.5 R211.2
N21978619: MH1.1 R111.2
N22046592: D38.C(CATHODE) J5.3
N22064922: D37.2(REF) R147.2 R149.2
N22064940: C58.1 Q4.1(GATE) R154.1 R221.2
N22064950: D37.1(CATHODE) R151.1 R221.1
N22064960: Q4.3(DRAIN) R79.1 R158.2
N22065002: C22.2 Q1.1(S1) Q1.3(S2) R73.1
N22065004: C22.1 R72.1 R73.2 R74.1 R78.1 R79.2
N22065156: C55.1 R152.1
N22065188: Q1.2(G1) R72.2
N22065200: Q1.4(G2) R74.2
N22070273: R148.2 U8.3(ISET)

Not connected (* = marked no-connect by the designer): CON3 A8(SBU1)* B8(SBU2)*; J10 4*; SDCARD1 MEC1* MEC2*; U4 4(DTR#)* 5(CTS#)* 6(RTS#)*

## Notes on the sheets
sheet 6
- DCIN&P5V
- 丝印DC5V
- Ilim (A)=6800 / Rset (ohm)
- Ilim (A)=1A
sheet 7
- USB2UART0
- 5V
sheet 8
- CONNECTOR
- gmac1_ptp_pps
- gmac1_ptp_trig
- USB
- UART
- gmac1_rx[3]
- gmac1_tx_ctl
- gmac1_rx[1]
- gmac1_rx[2]
- gmac1_rx_ctl
- gmac1_rx[0]
- gmac1_tx[2]
- gmac1_tx[3]
- gmac1_mdck
- gmac1_mdio
- gmac1_tx[0]
- gmac1_tx[1]
- I2C
- PHY0
- SDIO
- GMAC1
- CAN
- SPI
- LS2K0300
- TIM
- EJTAG
- ADC
- OTHER
- LCD
- I2S
sheet 9
- PIN EXTERNAL
- IIC X 4
- I2S X 1
- PWM X 4
- SPI X 2
- GMAC1 X 1
- AI X 8
- CAN X 4
- UART X 4
sheet 10
- EJTAG
- TF CARD SLOT
- RTC
- 丝印标注+-
- SPI0
sheet 11
- POWER DIAGRAM
sheet 12
- BLOCK DIAGRAM
